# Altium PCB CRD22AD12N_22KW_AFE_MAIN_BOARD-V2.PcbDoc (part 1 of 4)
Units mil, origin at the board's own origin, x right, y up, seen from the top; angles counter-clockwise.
Board outline 14411 x 7330.3 mil, 4 copper layers (TOP, GND02, POWER03, BOTTOM), stack 78.531 mil thick; 589 components, 281 nets, 1401 pads, 282 vias.
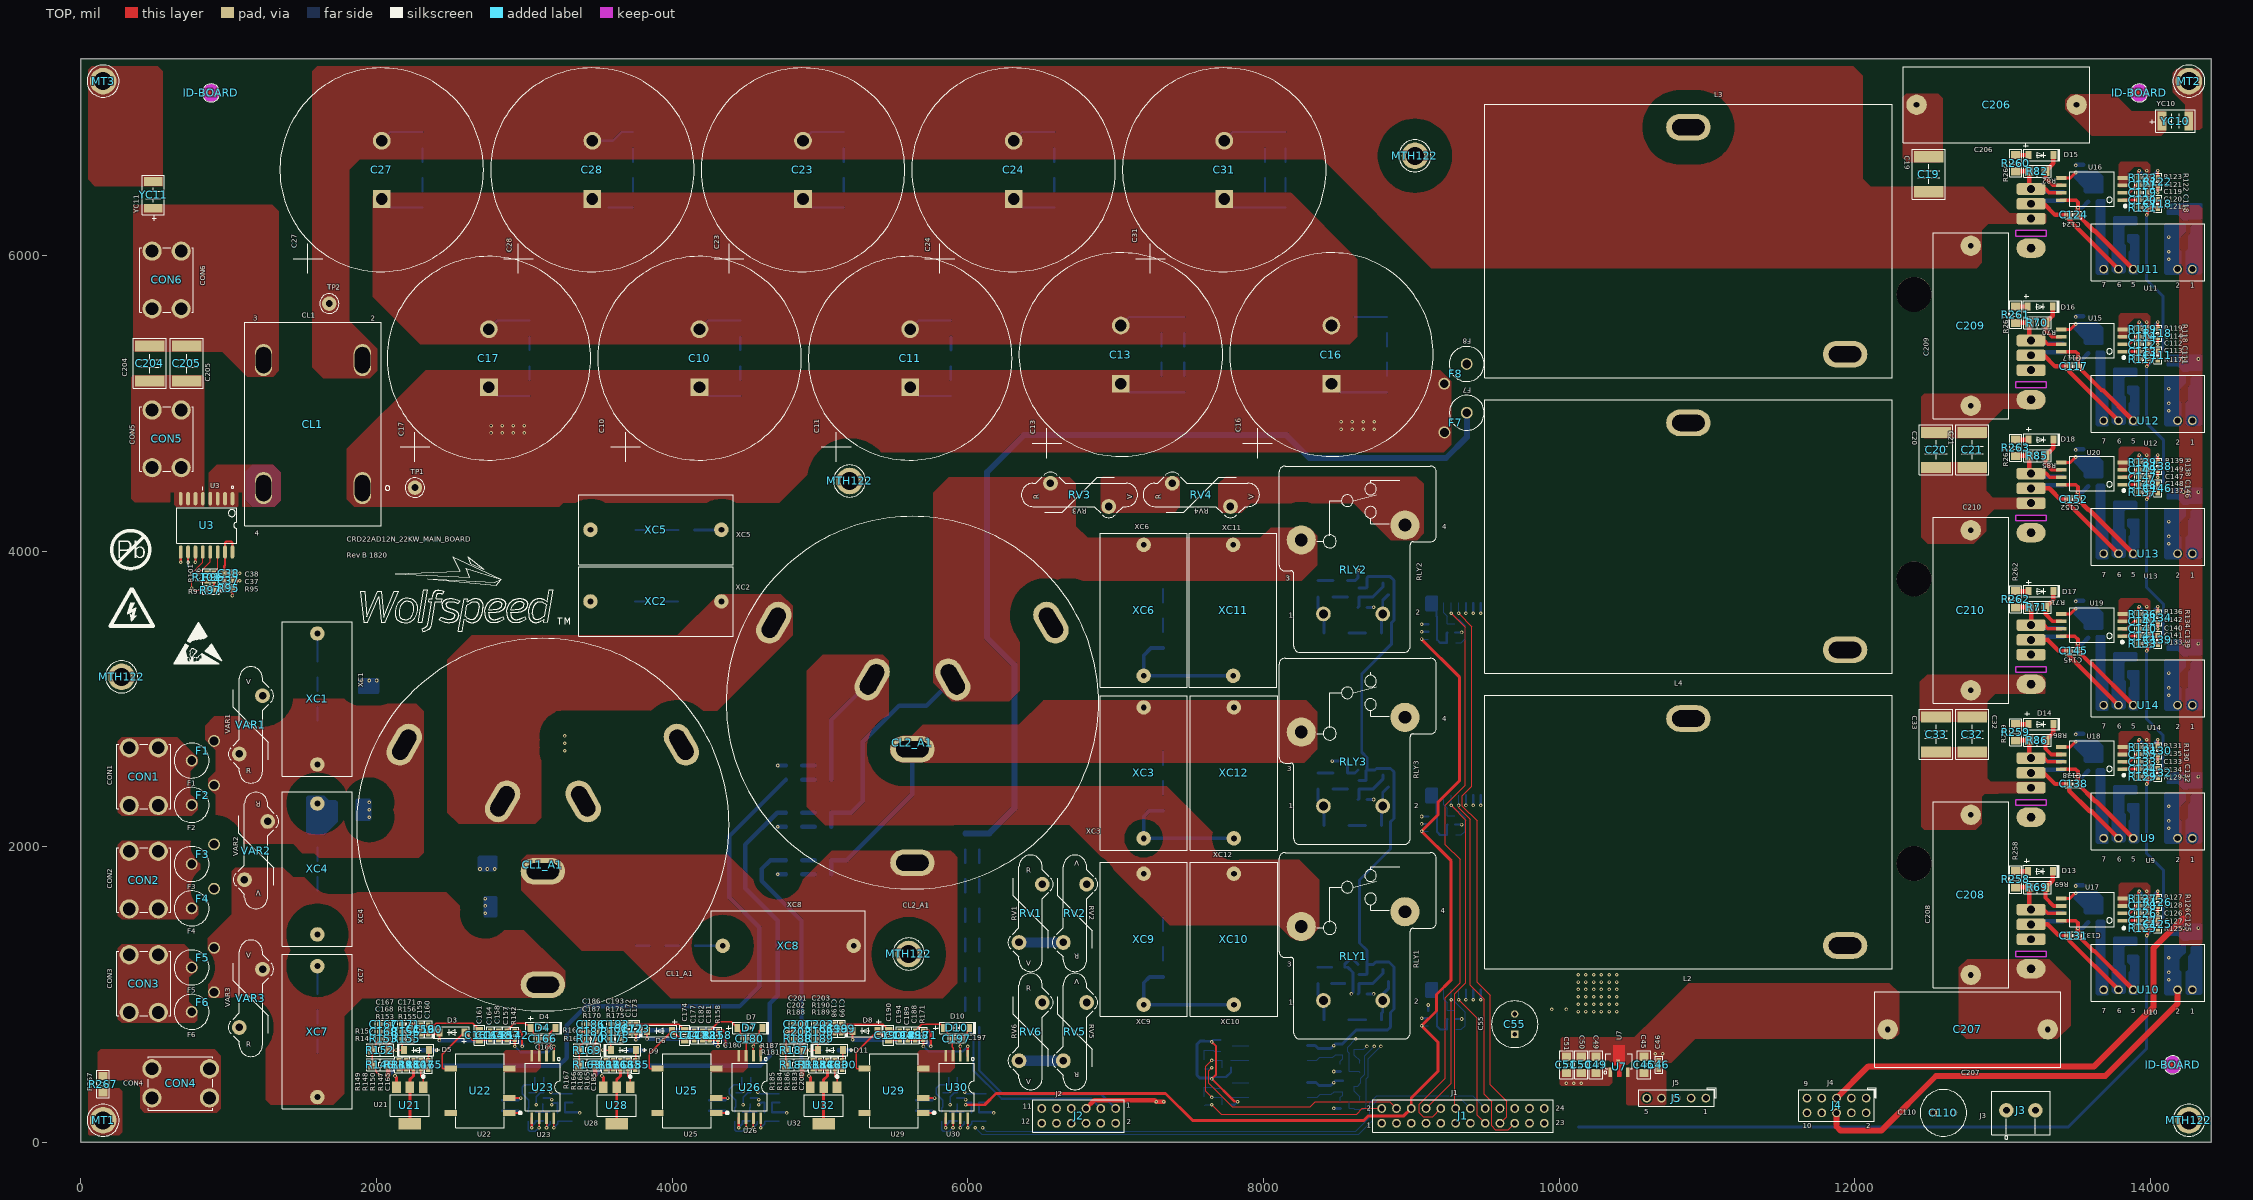
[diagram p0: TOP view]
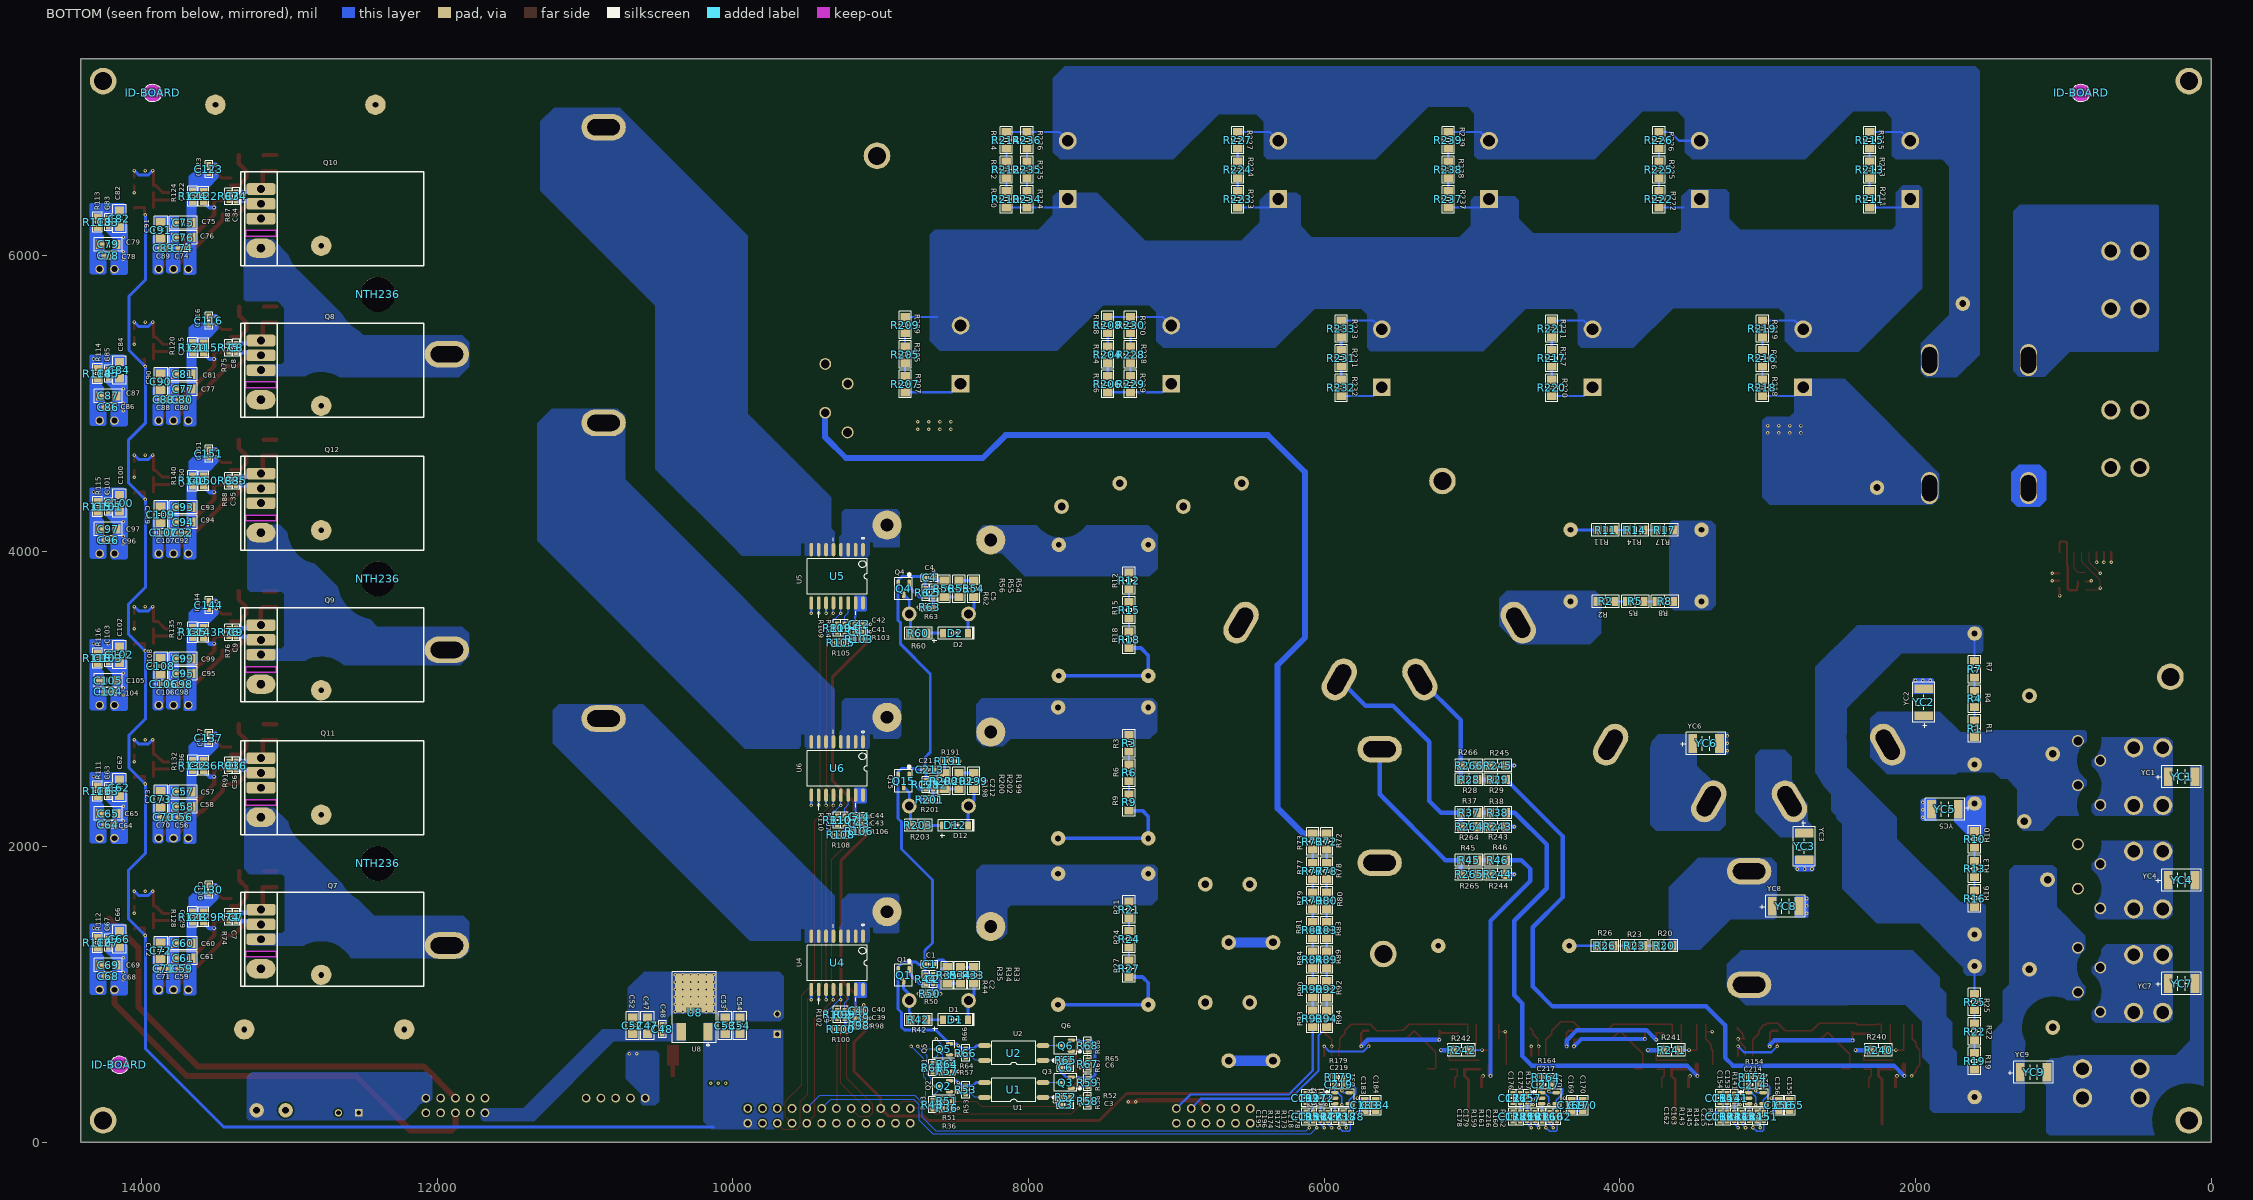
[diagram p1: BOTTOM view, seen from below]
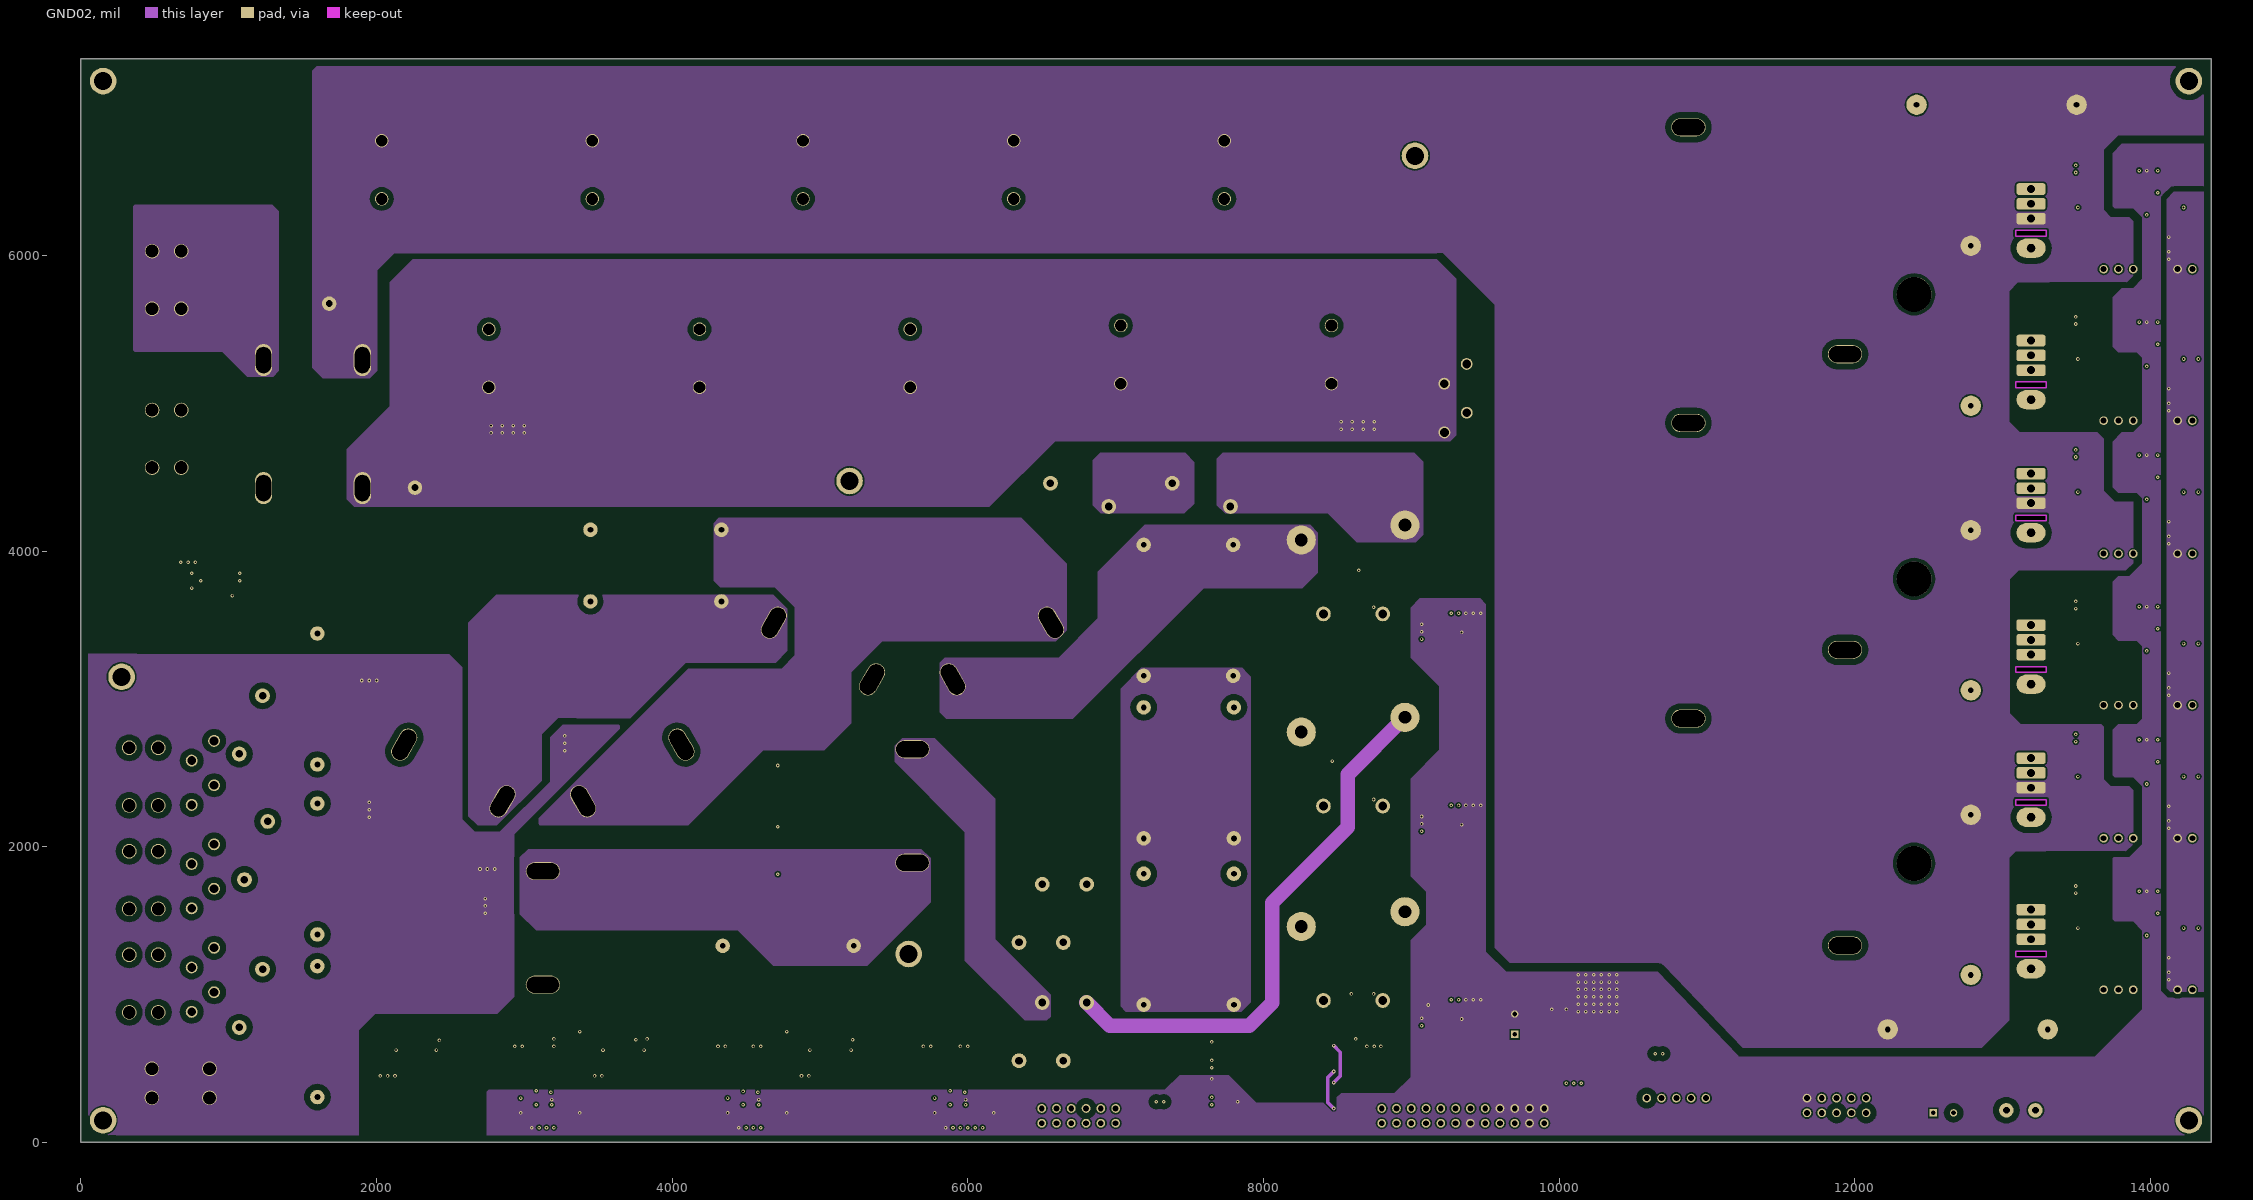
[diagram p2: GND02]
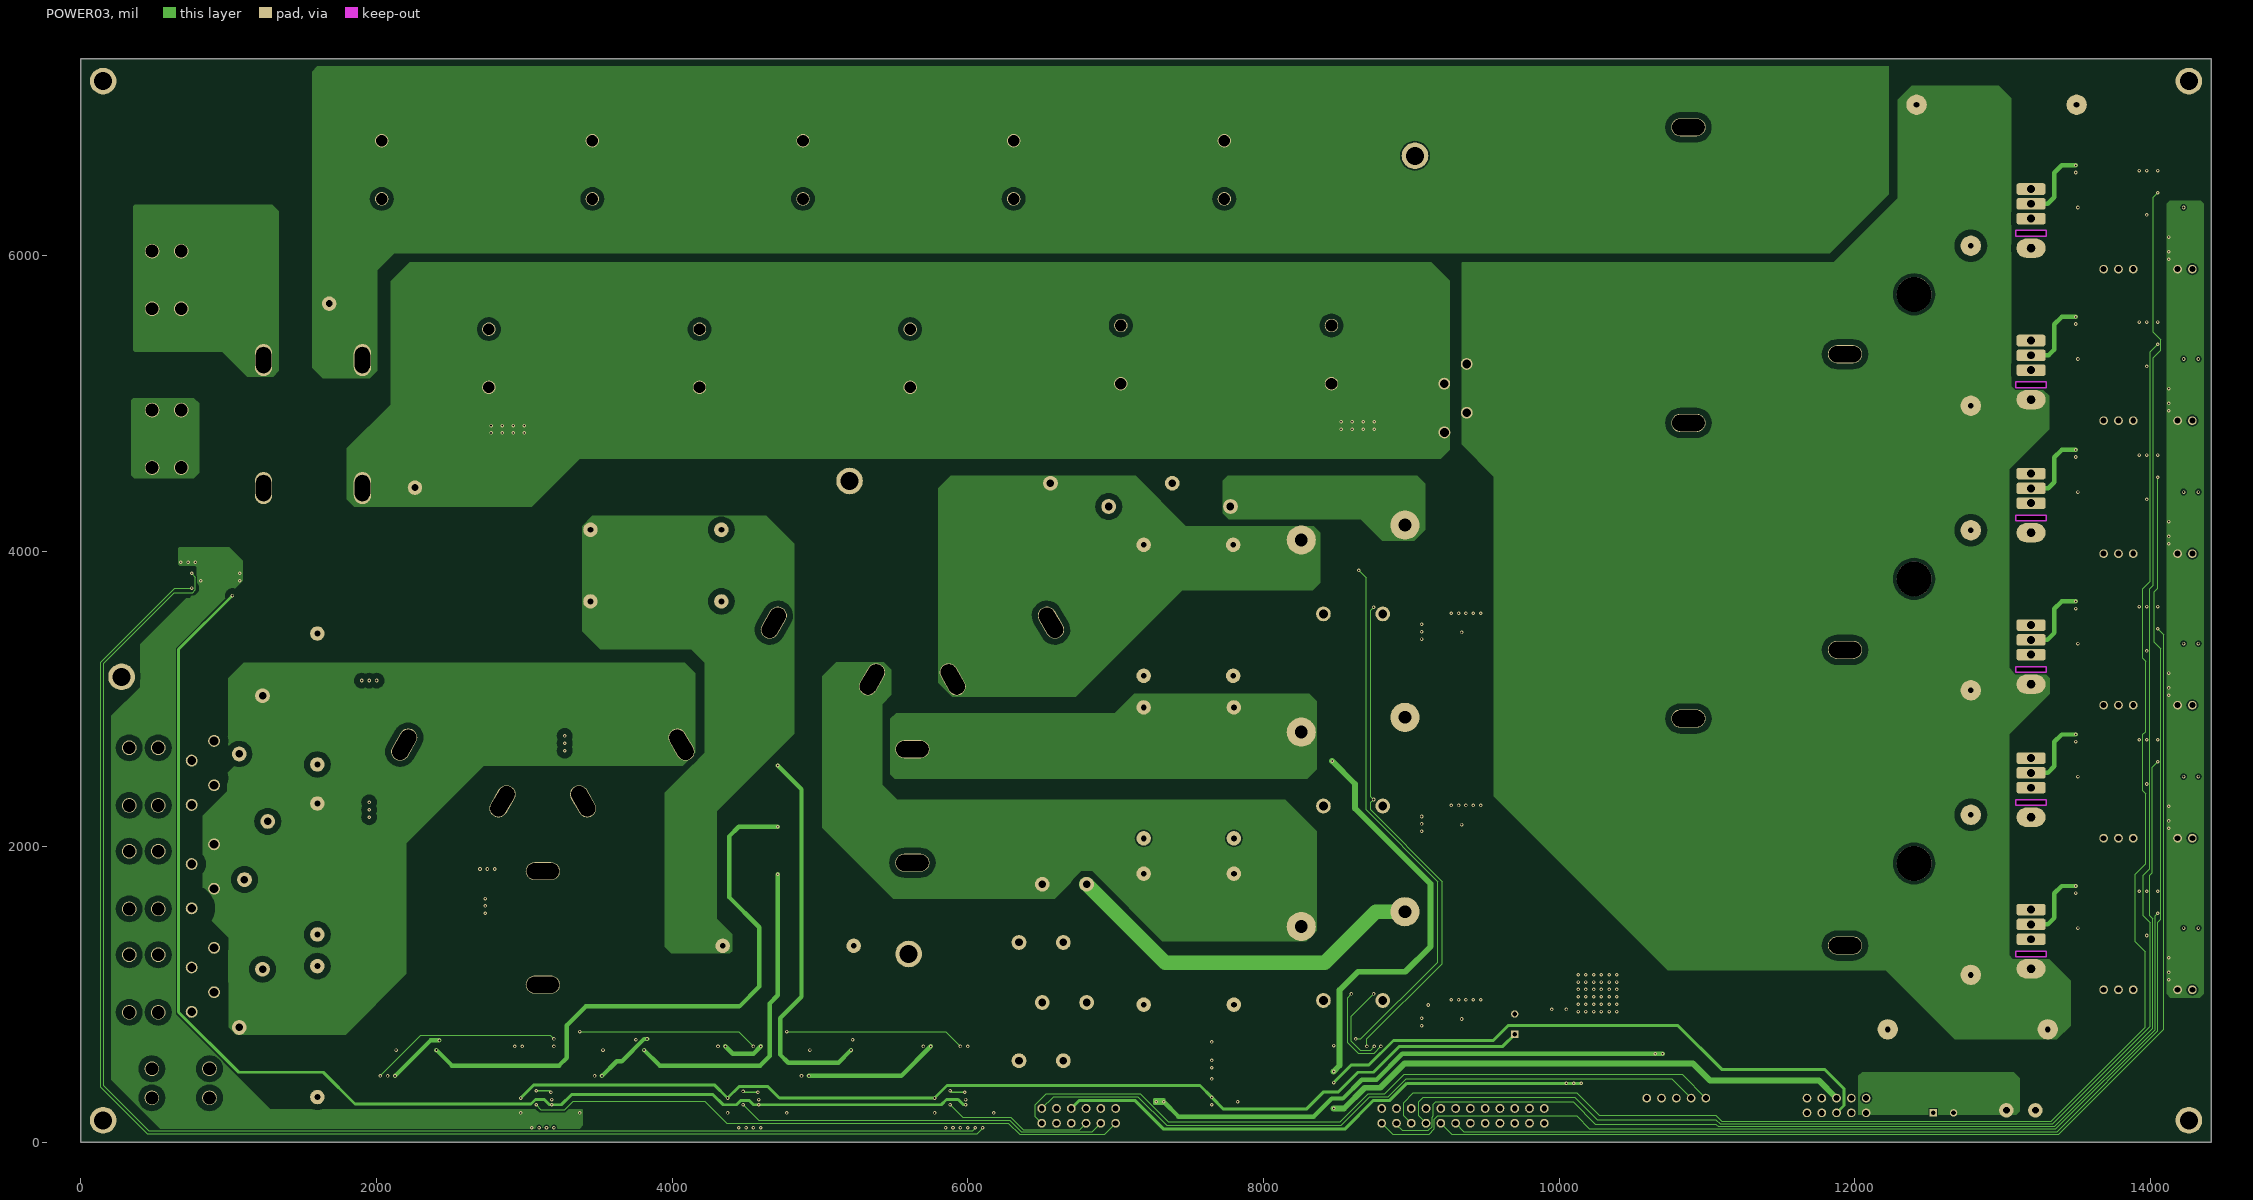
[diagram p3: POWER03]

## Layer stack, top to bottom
Top Solder: solder mask 0.4, Solder Resist, Dk 3.5
TOP: signal copper 2.7559
Dielectric 1: core 4.4153, FR-4, Dk 4.5
GND02: signal copper 2.4
Dielectric2: core 59.389, FR-4, Dk 4.5
POWER03: signal copper 2.4
Dielectric3: core 4.4153, FR-4, Dk 4.5
BOTTOM: signal copper 2.7559
Bottom Solder: solder mask 0.4, Solder Resist, Dk 3.5

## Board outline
0,7330.3 14411,7330.3 14411,0 0,0
cut-out: 13088.63,1255.32 13088.63,1294.68 13297.29,1294.68 13297.29,1255.32
cut-out: 13088.63,2280.31 13088.63,2319.68 13297.29,2319.68 13297.29,2280.31
cut-out: 13088.63,3180.32 13297.29,3180.32 13297.29,3219.68 13088.63,3219.68
cut-out: 13088.63,4205.31 13297.29,4205.31 13297.29,4244.68 13088.63,4244.68
cut-out: 13088.63,5105.31 13297.29,5105.31 13297.29,5144.68 13088.63,5144.68
cut-out: 13088.63,6130.31 13297.29,6130.31 13297.29,6169.68 13088.63,6169.68
cut-out: 13088.63,5144.68 13297.29,5144.68 13297.29,5105.31 13088.63,5105.31 13297.29,5105.31 13297.29,5144.68 13088.63,5144.68 13088.63,5105.31
cut-out: 13088.63,4244.68 13297.29,4244.68 13297.29,4205.31 13088.63,4205.31 13297.29,4205.31 13297.29,4244.68 13088.63,4244.68 13088.63,4205.31
cut-out: 13088.63,3219.68 13297.29,3219.68 13297.29,3180.32 13088.63,3180.32 13297.29,3180.32 13297.29,3219.68 13088.63,3219.68 13088.63,3180.32
cut-out: 13088.63,2319.68 13297.29,2319.68 13297.29,2280.31 13088.63,2280.31 13297.29,2280.31 13297.29,2319.68 13088.63,2319.68 13088.63,2280.31
cut-out: 13088.63,6169.68 13297.29,6169.68 13297.29,6130.31 13088.63,6130.31 13297.29,6130.31 13297.29,6169.68 13088.63,6169.68 13088.63,6130.31
cut-out: 13297.29,1255.31 13297.29,1294.68 13088.63,1294.68 13088.63,1255.31 13088.63,1294.68 13297.29,1294.68 13297.29,1255.31 13088.63,1255.31

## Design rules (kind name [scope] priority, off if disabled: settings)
Clearance "Clearance (Class DI-GAO)_INT" [(InNetClass('DI') AND OnLayer('Multi-Layer') OR OnLayer('GND02') OR OnLayer('POWER03')) vs (InNetClass('GAO') AND OnLayer('Multi-Layer') OR OnLayer('GND02') OR OnLayer('POWER03'))] p1: gap=40 ignorepadtopadclearanceinfootprint=FALSE except(5: Track-THPad Track-Via; 10: Arc-Arc Arc-Track Arc-SMDPad Arc-THPad Track-Track Track-SMDPad Track-Fill Track-Poly Track-Region Track-Text Track-Hole SMDPad-SMDPad SMDPad-THPad SMDPad-Via SMDPad-Fill SMDPad-Poly SMDPad-Region SMDPad-Text SMDPad-Hole; 12: Arc-Text THPad-Poly) // Internal Layers
Clearance Clearance_2 [All] p2: gap=10 ignorepadtopadclearanceinfootprint=FALSE except(0: SMDPad-Via Text-Hole; 5: Arc-Via Track-Via; 6: Track-Track Track-SMDPad Track-THPad; 8: Arc-Hole Track-Hole SMDPad-Hole THPad-Hole Via-Hole Fill-Hole Poly-Hole Region-Hole Hole-Hole; 9.1: SMDPad-SMDPad SMDPad-THPad THPad-THPad; 15: Fill-Poly Fill-Region Poly-Region)
Clearance "Clearance (Class DI-GAO)" [InNetClass('DI') vs InNetClass('GAO')] p3 off: gap=160 ignorepadtopadclearanceinfootprint=FALSE // (Class DI-GAO)
Clearance "Clearance for netlist (Same net)" [InNet('AC_LA') Or InNet('AC_LA1') Or InNet('AC_LAP') Or InNet('AC_LB') Or InNet('AC_LB1') Or InNet('AC_LBP') Or InNet('AC_LC') Or InNet('AC_LC1') Or InNet('AC_LCP') Or InNet('AGND') Or InNet('GGND') Or InNet('GND_EARTH') Or InNet('IGND') Or InNet('LA') Or InNet('LB') Or InNet('LC') Or InNet('N17896613') Or InNet('N17896948') Or InNet('N17898200') Or InNet('N17898311') Or InNet('N17908016') Or InNet('N17908018') Or InNet('N17908020') Or InNet('N17908062') Or InNet('N17911032') Or InNet('N17911109') Or InNet('N17911239') Or InNet('N17911323') Or InNet('N179113761') Or InNet('N17916066') Or InNet('N17916108') Or InNet('N17916243') Or InNet('N17920487') Or InNet('N18077724') Or InNet('N18077784') Or InNet('PGND') Or InNet('VPFC') vs InPolygon Or IsArc Or IsFill Or IsPad Or IsRegion Or IsThruPin Or IsThruVia Or IsTrack] p4 off: gap=10 ignorepadtopadclearanceinfootprint=FALSE except(0: Text-Hole; 5: Arc-Via Track-Via; 8: Arc-Hole Track-Hole SMDPad-Hole THPad-Hole Via-Hole Fill-Hole Poly-Hole Region-Hole Hole-Hole; 9.1: SMDPad-SMDPad SMDPad-THPad THPad-THPad; 15: Fill-Poly Fill-Region Poly-Region)
Clearance "Clearance for netlist" [InNet('AC_LA') Or InNet('AC_LA1') Or InNet('AC_LAP') Or InNet('AC_LB') Or InNet('AC_LB1') Or InNet('AC_LBP') Or InNet('AC_LC') Or InNet('AC_LC1') Or InNet('AC_LCP') Or InNet('AGND') Or InNet('GGND') Or InNet('GND_EARTH') Or InNet('IGND') Or InNet('LA') Or InNet('LB') Or InNet('LC') Or InNet('N17896613') Or InNet('N17896948') Or InNet('N17898200') Or InNet('N17898311') Or InNet('N17908016') Or InNet('N17908018') Or InNet('N17908020') Or InNet('N17908062') Or InNet('N17911032') Or InNet('N17911109') Or InNet('N17911239') Or InNet('N17911323') Or InNet('N179113761') Or InNet('N17916066') Or InNet('N17916108') Or InNet('N17916243') Or InNet('N17920487') Or InNet('N18077724') Or InNet('N18077784') Or InNet('PGND') Or InNet('VPFC') vs InPolygon Or IsArc Or IsFill Or IsPad Or IsRegion Or IsThruPin Or IsThruVia Or IsTrack] p5 off: gap=10 ignorepadtopadclearanceinfootprint=FALSE except(0: Text-Hole; 5: Arc-Via Track-Via; 8: Arc-Hole Track-Hole SMDPad-Hole THPad-Hole Via-Hole Fill-Hole Poly-Hole Region-Hole Hole-Hole; 9.1: SMDPad-SMDPad SMDPad-THPad THPad-THPad; 15: Fill-Poly Fill-Region Poly-Region)
Clearance "Clearance (Same Net)" [All] p6 off: gap=10 ignorepadtopadclearanceinfootprint=FALSE except(0: Arc-Fill Arc-Poly Arc-Region Track-Fill Track-Poly Track-Region SMDPad-Via SMDPad-Fill SMDPad-Poly SMDPad-Region Via-Fill Via-Poly Via-Region Fill-Poly Poly-Poly Text-Hole; 5: Arc-Via Track-Via; 8: Arc-Hole Track-Hole SMDPad-Hole THPad-Hole Via-Hole Fill-Hole Poly-Hole Region-Hole Hole-Hole; 9.1: SMDPad-SMDPad SMDPad-THPad THPad-THPad; 15: Fill-Fill Fill-Region Poly-Region Region-Region)
ComponentClearance [All] p1: gap=5 collisioncheckmode=3 verticalgap=10 showdistances=FALSE
Creepage [InNetClass('DI') vs InNetClass('GAO')] p1 off: checkdistance=160 ignoreinternallayers=FALSE // DI-GAO 160mil spacing
Height [All] p1: minheight=0 maxheight=3000 prefheight=500
HoleSize [All] p1: absolutevalues=TRUE maxlimit=250 minlimit=1 maxpercent=80.000 minpercent=20.000
PlaneConnect [All] p1: planeconnectstyle=Direct reliefexpansion=20 reliefentries=4 reliefconductorwidth=10 reliefairgap=10
PolygonConnect [All] p1: connectstyle=Direct reliefconductorwidth=10 reliefentries=4 polygonreliefangle="90 Angle" airgapwidth=10
RoutingVias [All] p1: holewidth=28 width=50 viastyle="Through Hole" minholewidth=28 minwidth=50 maxholewidth=28 maxwidth=50
SolderMaskExpansion [All] p1: expansion=4 istentingtop=FALSE
ViasUnderSMD [InComponent('U8')] p1: allowed=TRUE
Width [All] p1: maxlimit=300 minlimit=6 preferedwidth=10
26 further rules are at their usual default settings.

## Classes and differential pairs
net class R_DI: N17911032 N17911109 N17911239 N17911323 N18077724 N18077784 N179113761
net class DI: AGND GGND GND_EARTH IGND PGND
net class GAO: AC_LA AC_LA1 AC_LAP AC_LB AC_LB1 AC_LBP AC_LC AC_LC1 AC_LCP LA LB LC N17896613 N17896948 N17898200 N17898311 N17908016 N17908018 N17908020 N17908062 N17916066 N17916108 N17916243 N17920487 VPFC

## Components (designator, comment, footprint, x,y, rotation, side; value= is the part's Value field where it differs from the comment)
C1 "CAP NP_C0603_0.1UF" C0603 8670,1205 r0 bottom
C2 "CAP NP_C0603_1N" C0603 8645,1105 r270 bottom
C3 "CAP NP_C0603_0U1" C0603 7750,255 r0 bottom
C4 "CAP NP_C0603_0.1UF" C0603 8670,3820 r0 bottom
C5 "CAP NP_C0603_1N" C0603 8645,3720 r270 bottom
C6 "CAP NP_C0603_0U1" C0603 7750,505 r0 bottom
C7 "CAP NP_C0603_1N" C0603 13360.68,1525 r270 bottom
C8 "CAP NP_C0603_1N" C0603 13360.68,5375 r270 bottom
C9 "CAP NP_C0603_1N" C0603 13360.68,3450 r270 bottom
C10 "CAP POL_ECAP_D35P7_25_500V 680U" ECAP_D35P7_25 4185,5305 r90 top
C11 "CAP POL_ECAP_D35P7_25_500V 680U" ECAP_D35P7_25 5610,5305 r90 top
C13 "CAP POL_ECAP_D35P7_25_500V 680U" ECAP_D35P7_25 7035,5330 r90 top
C16 "CAP POL_ECAP_D35P7_25_500V 680U" ECAP_D35P7_25 8460,5330 r90 top
C17 "CAP POL_ECAP_D35P7_25_500V 680U" ECAP_D35P7_25 2760,5305 r90 top
C19 "CAP NP_C2220_0U1" C2220 12500,6550 r270 top
C20 "CAP NP_C2220_0U1" C2220 12550,4685 r270 top
C21 "CAP NP_C2220_0U1" C2220 12795,4685 r270 top
C23 "CAP POL_ECAP_D35P7_25_500V 680U" ECAP_D35P7_25 4885,6580 r90 top
C24 "CAP POL_ECAP_D35P7_25_500V 680U" ECAP_D35P7_25 6310,6580 r90 top
C27 "CAP POL_ECAP_D35P7_25_500V 680U" ECAP_D35P7_25 2035,6580 r90 top
C28 "CAP POL_ECAP_D35P7_25_500V 680U" ECAP_D35P7_25 3460,6580 r90 top
C31 "CAP POL_ECAP_D35P7_25_500V 680U" ECAP_D35P7_25 7735,6580 r90 top
C32 "CAP NP_C2220_0U1" C2220 12795,2760 r270 top
C33 "CAP NP_C2220_0U1" C2220 12550,2760 r270 top
C34 "CAP NP_C0603_1N" C0603 13360.68,6400 r270 bottom
C35 "CAP NP_C0603_1N" C0603 13360.68,4475 r270 bottom
C36 "CAP NP_C0603_1N" C0603 13360.68,2550 r270 bottom
C37 "CAP NP_C0603_0.1U" C0603 1000,3800 r0 top
C38 "CAP NP_C0603_1U" C0603 1000,3850 r0 top
C39 "CAP NP_C0603_0.1U" C0603 9145,840 r180 bottom
C40 "CAP NP_C0603_1U" C0603 9145,890 r180 bottom
C41 "CAP NP_C0603_0.1U" C0603 9145,3455 r180 bottom
C42 "CAP NP_C0603_1U" C0603 9145,3505 r180 bottom
C43 "CAP NP_C0603_0.1U" C0603 9145,2155 r180 bottom
C44 "CAP NP_C0603_1U" C0603 9145,2205 r180 bottom
C45 "CAP NP_C1206_10U" C1206 10575,525 r90 top
C46 "CAP NP_C0603_1U" C0603 10675,525 r270 top
C47 "CAP NP_C1206_10U" C1206 10577.76,790.75 r90 bottom
C48 "CAP NP_C0603_1U" C0603 10477.76,765.75 r270 bottom
C49 "CAP NP_C1206_1U" C1206 10250,525 r90 top
C50 "CAP NP_C1206_22U" C1206 10150,525 r90 top
C51 "CAP NP_C1206_22U" C1206 10050,525 r90 top
C52 "CAP NP_C1206_10U" C1206 10677.76,790.75 r90 bottom
C53 "CAP NP_C1206_10U" C1206 10052.76,790.75 r90 bottom
C54 "CAP NP_C1206_10U" C1206 9952.76,790.75 r90 bottom
C55 "CAP POL_ECAP_D8P3_5_25V 220UF" ECAP_D8P3_5 9700,800 r90 top
C56 "CAP NP_C0603_1UF" C0603 13725,2200 r0 bottom
C57 "CAP NP_C1206_4U7" C1206 13720,2372 r180 bottom
C58 "CAP NP_C1206_10UF" C1206 13720,2272 r180 bottom
C59 "CAP NP_C0603_1UF" C0603 13725,1175 r0 bottom
C60 "CAP NP_C1206_4U7" C1206 13720,1347 r180 bottom
C61 "CAP NP_C1206_10UF" C1206 13720,1247 r180 bottom
C62 "CAP NP_C1206_10UF" C1206 14150,2400 r90 bottom
C63 "CAP NP_C0603_1UF" C0603 14225,2375 r270 bottom
C64 "CAP NP_C0603_0U1" C0603 14225,2150 r180 bottom
C65 "CAP NP_C1206_2U2" C1206 14225,2225 r0 bottom
C66 "CAP NP_C1206_10UF" C1206 14150,1375 r90 bottom
C67 "CAP NP_C0603_1UF" C0603 14225,1350 r270 bottom
C68 "CAP NP_C0603_0U1" C0603 14225,1125 r180 bottom
C69 "CAP NP_C1206_2U2" C1206 14225,1200 r0 bottom
C70 "CAP NP_C0603_1UF" C0603 13850,2200 r0 bottom
C71 "CAP NP_C0603_1UF" C0603 13850,1175 r0 bottom
C72 "CAP NP_C1206_10UF" C1206 13870,1297 r90 bottom
C73 "CAP NP_C1206_10UF" C1206 13870,2322 r90 bottom
C74 "CAP NP_C0603_1UF" C0603 13725,6050 r0 bottom
C75 "CAP NP_C1206_4U7" C1206 13720,6222 r180 bottom
C76 "CAP NP_C1206_10UF" C1206 13720,6122 r180 bottom
C77 "CAP NP_C1206_10UF" C1206 13720,5097 r180 bottom
C78 "CAP NP_C0603_0U1" C0603 14225,6000 r180 bottom
C79 "CAP NP_C1206_2U2" C1206 14225,6075 r0 bottom
C80 "CAP NP_C0603_1UF" C0603 13725,5025 r0 bottom
C81 "CAP NP_C1206_4U7" C1206 13720,5197 r180 bottom
C82 "CAP NP_C1206_10UF" C1206 14150,6250 r90 bottom
C83 "CAP NP_C0603_1UF" C0603 14225,6225 r270 bottom
C84 "CAP NP_C1206_10UF" C1206 14150,5225 r90 bottom
C85 "CAP NP_C0603_1UF" C0603 14225,5200 r270 bottom
C86 "CAP NP_C0603_0U1" C0603 14225,4975 r180 bottom
C87 "CAP NP_C1206_2U2" C1206 14225,5050 r0 bottom
C88 "CAP NP_C0603_1UF" C0603 13850,5025 r0 bottom
C89 "CAP NP_C0603_1UF" C0603 13850,6050 r0 bottom
C90 "CAP NP_C1206_10UF" C1206 13870,5147 r90 bottom
C91 "CAP NP_C1206_10UF" C1206 13870,6172 r90 bottom
C92 "CAP NP_C0603_1UF" C0603 13725,4125 r0 bottom
C93 "CAP NP_C1206_4U7" C1206 13720,4297 r180 bottom
C94 "CAP NP_C1206_10UF" C1206 13720,4197 r180 bottom
C95 "CAP NP_C1206_10UF" C1206 13720,3172 r180 bottom
C96 "CAP NP_C0603_0U1" C0603 14225,4075 r180 bottom
C97 "CAP NP_C1206_2U2" C1206 14225,4150 r0 bottom
C98 "CAP NP_C0603_1UF" C0603 13725,3100 r0 bottom
C99 "CAP NP_C1206_4U7" C1206 13720,3272 r180 bottom
C100 "CAP NP_C1206_10UF" C1206 14150,4325 r90 bottom
C101 "CAP NP_C0603_1UF" C0603 14225,4300 r270 bottom
C102 "CAP NP_C1206_10UF" C1206 14150,3300 r90 bottom
C103 "CAP NP_C0603_1UF" C0603 14225,3275 r270 bottom
C104 "CAP NP_C0603_0U1" C0603 14225,3050 r180 bottom
C105 "CAP NP_C1206_2U2" C1206 14225,3125 r0 bottom
C106 "CAP NP_C0603_1UF" C0603 13850,3100 r0 bottom
C107 "CAP NP_C0603_1UF" C0603 13850,4125 r0 bottom
C108 "CAP NP_C1206_10UF" C1206 13870,3222 r90 bottom
C109 "CAP NP_C1206_10UF" C1206 13870,4247 r90 bottom
C110 "CAP POL_ECAP_D8P3_5_25V 220UF" ECAP_D8P3_5 12600,200 r0 top
C111 "CAP NP_C0603_2.2U" C0603 14050,5325 r90 top
C112 "CAP NP_C0603_1U" C0603 13950,5400 r0 top
C113 "CAP NP_C0603_0.1U" C0603 13950,5350 r0 top
C114 "CAP NP_C0603_0.33N" C0603 13950,5450 r0 top
C115 "CAP NP_C0805_2.2U" C0805 13580.34,5375 r270 bottom
C116 "CAP NP_C0603_1U" C0603 13545.34,5560 r90 bottom
C117 "CAP NP_C0603_1U" C0603 13480.34,5250 r0 top
C118 "CAP NP_C0603_2.2U" C0603 14050,6350 r90 top
C119 "CAP NP_C0603_1U" C0603 13950,6425 r0 top
C120 "CAP NP_C0603_0.1U" C0603 13950,6375 r0 top
C121 "CAP NP_C0603_0.33N" C0603 13950,6475 r0 top
C122 "CAP NP_C0805_2.2U" C0805 13580.34,6400 r270 bottom
C123 "CAP NP_C0603_1U" C0603 13545.34,6585 r90 bottom
C124 "CAP NP_C0603_1U" C0603 13480.34,6275 r0 top
C125 "CAP NP_C0603_2.2U" C0603 14050,1475 r90 top
C126 "CAP NP_C0603_1U" C0603 13950,1550 r0 top
C127 "CAP NP_C0603_0.1U" C0603 13950,1500 r0 top
C128 "CAP NP_C0603_0.33N" C0603 13950,1600 r0 top
C129 "CAP NP_C0805_2.2U" C0805 13580.34,1525 r270 bottom
C130 "CAP NP_C0603_1U" C0603 13545.34,1710 r90 bottom
C131 "CAP NP_C0603_1U" C0603 13480.34,1400 r0 top
C132 "CAP NP_C0603_2.2U" C0603 14050,2500 r90 top
C133 "CAP NP_C0603_1U" C0603 13950,2575 r0 top
C134 "CAP NP_C0603_0.1U" C0603 13950,2525 r0 top
C135 "CAP NP_C0603_0.33N" C0603 13950,2625 r0 top
C136 "CAP NP_C0805_2.2U" C0805 13580.34,2550 r270 bottom
C137 "CAP NP_C0603_1U" C0603 13545.34,2735 r90 bottom
C138 "CAP NP_C0603_1U" C0603 13480.34,2425 r0 top
C139 "CAP NP_C0603_2.2U" C0603 14050,3400 r90 top
C140 "CAP NP_C0603_1U" C0603 13950,3475 r0 top
C141 "CAP NP_C0603_0.1U" C0603 13950,3425 r0 top
C142 "CAP NP_C0603_0.33N" C0603 13950,3525 r0 top
C143 "CAP NP_C0805_2.2U" C0805 13580.34,3450 r270 bottom
C144 "CAP NP_C0603_1U" C0603 13545.34,3635 r90 bottom
C145 "CAP NP_C0603_1U" C0603 13480.34,3325 r0 top
C146 "CAP NP_C0603_2.2U" C0603 14050,4425 r90 top
C147 "CAP NP_C0603_1U" C0603 13950,4500 r0 top
C148 "CAP NP_C0603_0.1U" C0603 13950,4450 r0 top
C149 "CAP NP_C0603_0.33N" C0603 13950,4550 r0 top
C150 "CAP NP_C0805_2.2U" C0805 13580.34,4475 r270 bottom
C151 "CAP NP_C0603_1U" C0603 13545.34,4660 r90 bottom
C152 "CAP NP_C0603_1U" C0603 13480.34,4350 r0 top
C153 "CAP NP_C0603_0.1U" C0603 3275,300 r270 bottom
C154 "CAP NP_C0603_0.01U" C0603 3325,300 r270 bottom
C155 "CAP NP_C0805_4.7U" C0805 2850,250 r90 bottom
C156 "CAP NP_C0805_4.7U" C0805 2925,250 r90 bottom
C157 "CAP NP_C0603_0.1U" C0603 2880,725 r270 top
C158 "CAP NP_C0603_1U" C0603 2825,725 r270 top
C159 "CAP NP_C0603_0.1U" C0603 2300,765 r270 top
C160 "CAP NP_C0603_1U" C0603 2350,765 r270 top
C161 "CAP NP_C0805_4.7U" C0805 2695,725 r270 top
C162 "CAP NP_C0603_0.1U" C0603 3325,175 r90 bottom
C163 "CAP NP_C0603_0.01U" C0603 3275,175 r90 bottom
C164 "CAP NP_C0603_0.1U" C0603 2770,725 r270 top
C165 "CAP NP_C0603_0.1U" C0603 2350,525 r90 top
C166 "CAP NP_C0603_0.1U" C0603 3125,700 r180 top
C167 "CAP NP_C0603_0.1U" C0603 2050,800 r0 top
C168 "CAP NP_C0603_DNP" C0603 2050,750 r0 top
C169 "CAP NP_C0805_4.7U" C0805 4325,250 r90 bottom
C170 "CAP NP_C0805_4.7U" C0805 4250,250 r90 bottom
C171 "CAP NP_C0603_0.1U" C0603 2200,800 r0 top
C172 "CAP NP_C0603_0.1U" C0603 3705,770 r270 top
C173 "CAP NP_C0603_1U" C0603 3755,770 r270 top
C174 "CAP NP_C0805_4.7U" C0805 4085,725 r270 top
C175 "CAP NP_C0603_0.1U" C0603 4675,300 r270 bottom
C176 "CAP NP_C0603_0.01U" C0603 4725,300 r270 bottom
C177 "CAP NP_C0603_0.1U" C0603 4150,725 r270 top
C178 "CAP NP_C0603_0.1U" C0603 4725,175 r90 bottom
C179 "CAP NP_C0603_0.01U" C0603 4675,175 r90 bottom
C180 "CAP NP_C0603_0.1U" C0603 4525,700 r180 top
C181 "CAP NP_C0603_0.1U" C0603 4255,725 r270 top
C182 "CAP NP_C0603_1U" C0603 4205,725 r270 top
C183 "CAP NP_C0805_4.7U" C0805 5725,250 r90 bottom
C184 "CAP NP_C0805_4.7U" C0805 5650,250 r90 bottom
C185 "CAP NP_C0603_0.1U" C0603 3750,525 r90 top
C186 "CAP NP_C0603_0.1U" C0603 3450,800 r0 top
C187 "CAP NP_C0603_DNP" C0603 3450,750 r0 top
C188 "CAP NP_C0603_0.1U" C0603 5645,725 r270 top
C189 "CAP NP_C0603_1U" C0603 5595,725 r270 top
C190 "CAP NP_C0805_4.7U" C0805 5465,725 r270 top
C191 "CAP NP_C0603_0.1U" C0603 6075,300 r270 bottom
C192 "CAP NP_C0603_0.01U" C0603 6125,300 r270 bottom
C193 "CAP NP_C0603_0.1U" C0603 3615,800 r0 top
C194 "CAP NP_C0603_0.1U" C0603 5540,725 r270 top
C195 "CAP NP_C0603_0.1U" C0603 6125,175 r90 bottom
C196 "CAP NP_C0603_0.01U" C0603 6075,175 r90 bottom
C197 "CAP NP_C0603_0.1U" C0603 5925,700 r180 top
C198 "CAP NP_C0603_0.1U" C0603 5095,770 r270 top
C199 "CAP NP_C0603_1U" C0603 5145,770 r270 top
C200 "CAP NP_C0603_0.1U" C0603 5150,525 r90 top
C201 "CAP NP_C0603_0.1U" C0603 4850,800 r0 top
C202 "CAP NP_C0603_DNP" C0603 4850,750 r0 top
C203 "CAP NP_C0603_0.1U" C0603 5000,800 r0 top
C204 "CAP NP_C2220_0U1" C2220 465,5270 r90 top
C205 "CAP NP_C2220_0U1" C2220 715,5270 r90 top
C206 "CAP NP_CAPFILM_31_5X12_5MM_2.2U" CAPFILM_31_5X12_5MM 12960,7020 r0 top
C207 "CAP NP_CAPFILM_31_5X12_5MM_2.2U" CAPFILM_31_5X12_5MM 12765,765 r180 top
C208 "CAP NP_CAPFILM_31_5X12_5MM_2.2U" CAPFILM_31_5X12_5MM 12785.68,1675 r90 top
C209 "CAP NP_CAPFILM_31_5X12_5MM_2.2U" CAPFILM_31_5X12_5MM 12785.68,5525 r90 top
C210 "CAP NP_CAPFILM_31_5X12_5MM_2.2U" CAPFILM_31_5X12_5MM 12785.68,3600 r90 top
C212 "CAP NP_C0603_1N" C0603 8645,2420 r270 bottom
C213 "CAP NP_C0603_0.1UF" C0603 8670,2520 r0 bottom
C214 "CAP NP_C0603_NA" C0603 3100,390 r0 bottom
C215 "CAP NP_C0603_NA" C0603 3075,175 r270 bottom
C216 "CAP NP_C0603_NA" C0603 4525,175 r270 bottom
C217 "CAP NP_C0603_NA" C0603 4500,390 r0 bottom
C218 "CAP NP_C0603_NA" C0603 5875,175 r270 bottom
C219 "CAP NP_C0603_NA" C0603 5900,390 r0 bottom
CL1 "TRNSFMR 67125450_0_CM_4P_6TS" CM_4P 1570,4860 r90 top
CL1_A1 "126LNS_5_LCM1_8U" LCM1 3125,2150 r0 top
CL2_A1 "126LNS_5_LCM1_8U" LCM1 5625,2975 r0 top
CON1 "CONNECTER_THREAD4_9P9X5_1110X92" THREAD4_9P9X5_1110X920 425,2475 r270 top
CON2 "CONNECTER_THREAD4_9P9X5_1110X92" THREAD4_9P9X5_1110X920 425,1775 r270 top
CON3 "CONNECTER_THREAD4_9P9X5_1110X92" THREAD4_9P9X5_1110X920 425,1075 r270 top
CON4 "CONNECTER_THREAD4_9P9X5_1110X92" THREAD4_9P9X5_1110X920 675,400 r0 top
CON5 "CONNECTER_THREAD4_9P9X5_1110X92" THREAD4_9P9X5_1110X920 580,4760 r90 top
CON6 "CONNECTER_THREAD4_9P9X5_1110X92" THREAD4_9P9X5_1110X920 580,5835 r270 top
D1 "DIODE_0_SOD-123_1N4148W" SOD-123#1 8495,830 r0 bottom
D2 "DIODE_0_SOD-123_1N4148W" SOD-123#1 8495,3445 r0 bottom
D3 "BAS21/SOT_1_SOD-123_MBR0530TR" SOD-123#2 2510,745 r180 top
D4 "DIODE ZENER_0_SOD-123_DNP" SOD-123#2 3125,775 r0 top
D5 "BAS21/SOT_1_SOD-123_BAT46W-E3-G" SOD-123#2 2270,625 r180 top
D6 "BAS21/SOT_1_SOD-123_MBR0530TR" SOD-123#2 3915,755 r180 top
D7 "DIODE ZENER_0_SOD-123_DNP" SOD-123#2 4525,775 r0 top
D8 "BAS21/SOT_1_SOD-123_MBR0530TR" SOD-123#2 5305,755 r180 top
D9 "BAS21/SOT_1_SOD-123_BAT46W-E3-G" SOD-123#2 3670,625 r180 top
D10 "DIODE ZENER_0_SOD-123_DNP" SOD-123#2 5925,775 r0 top
D11 "BAS21/SOT_1_SOD-123_BAT46W-E3-G" SOD-123#2 5070,625 r180 top
D12 "DIODE_0_SOD-123_1N4148W" SOD-123#1 8495,2145 r0 bottom
D13 "DIODE_0_SOD-123_SL14PL-TP" SOD-123#2 13255.68,1835 r0 top
D14 "DIODE_0_SOD-123_SL14PL-TP" SOD-123#2 13260,2830 r0 top
D15 "DIODE_0_SOD-123_SL14PL-TP" SOD-123#2 13260,6680 r0 top
D16 "DIODE_0_SOD-123_SL14PL-TP" SOD-123#2 13255,5655 r0 top
D17 "DIODE_0_SOD-123_SL14PL-TP" SOD-123#2 13260,3730 r0 top
D18 "DIODE_0_SOD-123_SL14PL-TP" SOD-123#2 13260,4755 r0 top
F1 "FUSE_0_FULSE_25A" FULSE 825,2650 r180 top
F2 "FUSE_0_FULSE_25A" FULSE 825,2350 r180 top
F3 "FUSE_0_FULSE_25A" FULSE 825,1950 r180 top
F4 "FUSE_0_FULSE_25A" FULSE 825,1650 r180 top
F5 "FUSE_0_FULSE_25A" FULSE 825,1250 r180 top
F6 "FUSE_0_FULSE_25A" FULSE 825,950 r180 top
F7 "FUSE_0_FULSE_25A" FULSE 9300,4870 r0 top
F8 "FUSE_0_FULSE_25A" FULSE 9299.35,5200 r0 top
ID-BOARD "#DEV" ID-BOARD 13925,7100 r0 top
ID-BOARD "#DEV" ID-BOARD 880,7100 r0 top
ID-BOARD "#DEV" ID-BOARD 14150,525 r0 top
ID-BOARD "#DEV" ID-BOARD 13925,7100 r0 bottom
ID-BOARD "#DEV" ID-BOARD 880,7100 r0 bottom
ID-BOARD "#DEV" ID-BOARD 14150,525 r0 bottom
J1 "CON24A_CON_2MM54_12X2_CON24A" CON_2MM54_12X2 9350,180 r0 top
J2 "CON12A_CON_2MM54_6X2_CON12A" CON_2MM54_6X2 6750,180 r180 top
J3 "CON2_CON_5MM_2X1_CON2" CON_5MM_2X1 13125,200 r0 top
J4 "CON10A_CON_2MM54_5X2_CON10A" CON_2MM54_5X2 11884.1,256.89 r180 top
J5 "CON5_CON_2MM54_5X1_CON5" CON_2MM54_5X1 10800,306.89 r180 top
L2 "126LNS_1_L71MM_8U" L71MM 10875,2100 r90 top
L3 "126LNS_1_L71MM_8U" L71MM 10875,6100 r90 top
L4 "126LNS_1_L71MM_8U" L71MM 10875,4100 r90 top
MT1 "CON1_2_MTH122_T1T2" MTH122 150,150 r90 top
MT2 "CON1_2_MTH122_T1T2" MTH122 14261,7180.3 r90 top
MT3 "CON1_2_MTH122_T1T2" MTH122 150,7180.3 r90 top
MTH122 "CON1_2_MTH122_T1T2" MTH122 14261,150 r90 top
MTH122 "CON1_2_MTH122_T1T2" MTH122 5200,4475 r90 top
MTH122 "CON1_2_MTH122_T1T2" MTH122 275,3150 r90 top
MTH122 "CON1_2_MTH122_T1T2" MTH122 9025,6675 r90 top
MTH122 "CON1_2_MTH122_T1T2" MTH122 5600,1275 r90 top
NTH236 "" NTH236 12401.82,1887.5 r0 bottom
NTH236 "" NTH236 12401.82,3812.5 r0 bottom
NTH236 "" NTH236 12401.82,5737.5 r0 bottom
Q1 "2N7002/SOT_SOT-23_2N7002K" SOT-23 8845,1130 r0 bottom
Q2 "2N7002/SOT_SOT-23_2N7002K" SOT-23 8575,380 r90 bottom
Q3 "2N7002/SOT_SOT-23_2N7002K" SOT-23 7750,405 r90 bottom
Q4 "2N7002/SOT_SOT-23_2N7002K" SOT-23 8845,3745 r0 bottom
Q5 "2N7002/SOT_SOT-23_2N7002K" SOT-23 8575,630 r90 bottom
Q6 "2N7002/SOT_SOT-23_2N7002K" SOT-23 7750,655 r90 bottom
Q7 "C3M0065090J_4_TO-247-4L_C3M0032" TO-247-4L 12710.68,1375 r90 bottom
Q8 "C3M0065090J_4_TO-247-4L_C3M0032" TO-247-4L 12710.68,5225 r90 bottom
Q9 "C3M0065090J_4_TO-247-4L_C3M0021" TO-247-4L 12710.68,3300 r90 bottom
Q10 "C3M0065090J_4_TO-247-4L_C3M0032" TO-247-4L 12710.68,6250 r90 bottom
Q11 "C3M0065090J_4_TO-247-4L_C3M0032" TO-247-4L 12710.68,2400 r90 bottom
Q12 "C3M0065090J_4_TO-247-4L_C3M0021" TO-247-4L 12710.68,4325 r90 bottom
Q15 "2N7002/SOT_SOT-23_2N7002K" SOT-23 8845,2445 r0 bottom
R1 "R_2_R1206_360K" R1206 1600,2800 r270 bottom
R2 "R_2_R1206_360K" R1206 4095,3660 r0 bottom
R3 "R_2_R1206_360K" R1206 7320,2700 r90 bottom
R4 "R_2_R1206_360K" R1206 1600,3000 r270 bottom
R5 "R_2_R1206_360K" R1206 3895,3660 r0 bottom
R6 "R_2_R1206_360K" R1206 7320,2500 r90 bottom
R7 "R_2_R1206_360K" R1206 1600,3200 r270 bottom
R8 "R_2_R1206_360K" R1206 3695,3660 r0 bottom
R9 "R_2_R1206_360K" R1206 7320,2300 r90 bottom
R10 "R_2_R1206_360K" R1206 1600,2050 r90 bottom
R11 "R_2_R1206_360K" R1206 4096,4143 r0 bottom
R12 "R_2_R1206_360K" R1206 7320,3800 r90 bottom
R13 "R_2_R1206_360K" R1206 1600,1850 r90 bottom
R14 "R_2_R1206_360K" R1206 3896,4143 r0 bottom
R15 "R_2_R1206_360K" R1206 7320,3600 r90 bottom
R16 "R_2_R1206_360K" R1206 1600,1650 r90 bottom
R17 "R_2_R1206_360K" R1206 3696,4143 r0 bottom
R18 "R_2_R1206_360K" R1206 7320,3400 r90 bottom
R19 "R_2_R1206_360K" R1206 1600,550 r270 bottom
R20 "R_2_R1206_360K" R1206 3700,1330 r180 bottom
R21 "R_2_R1206_360K" R1206 7320,1575 r90 bottom
R22 "R_2_R1206_360K" R1206 1600,750 r270 bottom
R23 "R_2_R1206_360K" R1206 3900,1330 r180 bottom
R24 "R_2_R1206_360K" R1206 7320,1375 r90 bottom
R25 "R_2_R1206_360K" R1206 1600,950 r270 bottom
R26 "R_2_R1206_360K" R1206 4100,1330 r180 bottom
R27 "R_2_R1206_360K" R1206 7320,1175 r90 bottom
R28 "RESISTOR_R1206_220K" R1206 5020,2455 r180 bottom
R29 "RESISTOR_R1206_220K" R1206 4825,2455 r180 bottom
R33 "RESISTOR_R1206_15R" R1206 8370,1130 r90 bottom
R34 "RESISTOR_R1206_15R" R1206 8460,1130 r270 bottom
R35 "RESISTOR_R1206_15R" R1206 8550,1130 r90 bottom
R36 "RESISTOR_R0603_0R" R0603 8550,230 r0 bottom
R37 "RESISTOR_R1206_220K" R1206 5020,2230 r180 bottom
R38 "RESISTOR_R1206_220K" R1206 4825,2230 r180 bottom
R42 "RESISTOR_R1206_22" R1206 8745,830 r0 bottom
R43 "RESISTOR_R0603_10K" R0603 8650,255 r270 bottom
R44 "RESISTOR_R0603_10K" R0603 8695,1105 r90 bottom
R45 "RESISTOR_R1206_220K" R1206 5020,1910 r180 bottom
R46 "RESISTOR_R1206_220K" R1206 4825,1910 r180 bottom
R50 "RESISTOR_R0603_1K" R0603 8670,1005 r0 bottom
R51 "RESISTOR_R0603_10K" R0603 8550,280 r0 bottom
R52 "RESISTOR_R0603_1K" R0603 7750,305 r180 bottom
R53 "RESISTOR_R0603_20K" R0603 8425,355 r270 bottom
R54 "RESISTOR_R1206_15R" R1206 8370,3745 r90 bottom
R55 "RESISTOR_R1206_15R" R1206 8470,3745 r270 bottom
R56 "RESISTOR_R1206_15R" R1206 8570,3745 r90 bottom
R57 "RESISTOR_R0603_0R" R0603 8550,480 r0 bottom
R58 "RESISTOR_R0603_220R" R0603 7600,280 r270 bottom
R59 "RESISTOR_R0603_10K" R0603 7600,405 r270 bottom
R60 "RESISTOR_R1206_22" R1206 8745,3445 r0 bottom
R61 "RESISTOR_R0603_5K" R0603 8650,505 r270 bottom
R62 "RESISTOR_R0603_10K" R0603 8695,3720 r90 bottom
R63 "RESISTOR_R0603_1K" R0603 8670,3620 r0 bottom
R64 "RESISTOR_R0603_10K" R0603 8550,530 r0 bottom
R65 "RESISTOR_R0603_1K" R0603 7750,555 r180 bottom
R66 "RESISTOR_R0603_20K" R0603 8425,605 r270 bottom
R67 "RESISTOR_R0603_220R" R0603 7600,530 r270 bottom
R68 "RESISTOR_R0603_10K" R0603 7600,655 r270 bottom
R69 "R_R1206_6R8" R1206 13235.68,1725 r180 top
R70 "R_R1206_6R8" R1206 13235.68,5545 r180 top
R71 "R_R1206_6R8" R1206 13235.68,3620 r180 top
R72 "RESISTOR_R1206_0R" R1206 5982.76,2035.75 r90 bottom
R73 "RESISTOR_R1206_0" R1206 6077.76,2035.75 r90 bottom
R74 "R_R0603_10K" R0603 13410.68,1525 r90 bottom
R75 "R_R0603_10K" R0603 13410.68,5375 r90 bottom
R76 "R_R0603_10K" R0603 13410.68,3450 r90 bottom
R77 "RESISTOR_R1206_620K" R1206 6077.76,1835.75 r90 bottom
R78 "RESISTOR_R1206_620K" R1206 5982.76,1835.75 r90 bottom
R79 "RESISTOR_R1206_620K" R1206 6077.76,1635.75 r90 bottom
R80 "RESISTOR_R1206_620K" R1206 5982.76,1635.75 r90 bottom
R81 "RESISTOR_R1206_620K" R1206 6077.76,1435.75 r90 bottom
R82 "R_R1206_6R8" R1206 13235.68,6570 r180 top
R83 "RESISTOR_R1206_620K" R1206 5982.76,1435.75 r90 bottom
R84 "RESISTOR_R1206_620K" R1206 6077.76,1235.75 r90 bottom
R85 "R_R1206_6R8" R1206 13235.68,4645 r180 top
R86 "R_R1206_6R8" R1206 13235.68,2720 r180 top
R87 "R_R0603_10K" R0603 13410.68,6400 r90 bottom
R88 "R_R0603_10K" R0603 13410.68,4475 r90 bottom
R89 "RESISTOR_R1206_620K" R1206 5982.76,1235.75 r90 bottom
R90 "RESISTOR_R1206_620K" R1206 6077.76,1035.75 r90 bottom
R91 "R_R0603_10K" R0603 13410.68,2550 r90 bottom
R92 "RESISTOR_R1206_620K" R1206 5982.76,1035.75 r90 bottom
R93 "RESISTOR_R1206_620K" R1206 6077.76,835.75 r90 bottom
R94 "RESISTOR_R1206_620K" R1206 5982.76,835.75 r90 bottom
R95 "R_R0603_10R" R0603 1000,3750 r180 top
R96 "R_R0603_6.8K" R0603 900,3825 r90 top
R97 "R_R0603_10K" R0603 880,3735 r180 top
R98 "R_R0603_10R" R0603 9145,790 r0 bottom
R99 "R_R0603_6.8K" R0603 9245,865 r90 bottom
R100 "R_R0603_10K" R0603 9270,765 r0 bottom
R101 "R_R0603_1.8K" R0603 850,3825 r270 top
R102 "R_R0603_1.8K" R0603 9295,865 r270 bottom
R103 "R_R0603_10R" R0603 9145,3405 r0 bottom
R104 "R_R0603_6.8K" R0603 9245,3480 r90 bottom
R105 "R_R0603_10K" R0603 9270,3380 r0 bottom
R106 "R_R0603_10R" R0603 9145,2105 r0 bottom
R107 "R_R0603_6.8K" R0603 9245,2180 r90 bottom
R108 "R_R0603_10K" R0603 9270,2080 r0 bottom
R109 "R_R0603_1.8K" R0603 9295,3480 r270 bottom
R110 "R_R0603_1.8K" R0603 9295,2180 r270 bottom
R111 "RESISTOR_R0805_1R" R0805 14300,2375 r90 bottom
R112 "RESISTOR_R0805_1R" R0805 14300,1350 r90 bottom
R113 "RESISTOR_R0805_1R" R0805 14300,6225 r90 bottom
R114 "RESISTOR_R0805_1R" R0805 14300,5200 r90 bottom
R115 "RESISTOR_R0805_1R" R0805 14300,4300 r90 bottom
R116 "RESISTOR_R0805_1R" R0805 14300,3275 r90 bottom
R117 "R_R0603_10R" R0603 13950,5300 r180 top
R118 "RESISTOR_R0603_100" R0603 14050,5475 r90 top
R119 "RESISTOR_R0603_4.7K" R0603 13950,5500 r0 top
R120 "R_R0805_1R" R0805 13655.34,5375 r270 bottom
R121 "R_R0603_10R" R0603 13950,6325 r180 top
R122 "RESISTOR_R0603_100" R0603 14050,6500 r90 top
R123 "RESISTOR_R0603_4.7K" R0603 13950,6525 r0 top
R124 "R_R0805_1R" R0805 13655.34,6400 r270 bottom
R125 "R_R0603_10R" R0603 13950,1450 r180 top
R126 "RESISTOR_R0603_100" R0603 14050,1625 r90 top
R127 "RESISTOR_R0603_4.7K" R0603 13950,1650 r0 top
R128 "R_R0805_1R" R0805 13655.34,1525 r270 bottom
R129 "R_R0603_10R" R0603 13950,2475 r180 top
R130 "RESISTOR_R0603_100" R0603 14050,2650 r90 top
R131 "RESISTOR_R0603_4.7K" R0603 13950,2675 r0 top
R132 "R_R0805_1R" R0805 13655.34,2550 r270 bottom
R133 "R_R0603_10R" R0603 13950,3375 r180 top
R134 "RESISTOR_R0603_100" R0603 14050,3550 r90 top
R135 "R_R0805_1R" R0805 13655.34,3450 r270 bottom
R136 "RESISTOR_R0603_4.7K" R0603 13950,3575 r0 top
R137 "R_R0603_10R" R0603 13950,4400 r180 top
R138 "RESISTOR_R0603_100" R0603 14050,4575 r90 top
R139 "RESISTOR_R0603_4.7K" R0603 13950,4600 r0 top
R140 "R_R0805_1R" R0805 13655.34,4475 r270 bottom
R141 "RESISTOR_R0603_4.7" R0603 3225,300 r90 bottom
R142 "RESISTOR_R0603_4.7" R0603 2935,725 r270 top
R143 "RESISTOR_R0603_4.7" R0603 3225,175 r270 bottom
R144 "RESISTOR_R0603_10K" R0603 3125,175 r270 bottom
R145 "RESISTOR_R0603_10K" R0603 3175,175 r90 bottom
R146 "RESISTOR_R1206_220K" R1206 2025,525 r180 top
R147 "RESISTOR_R0603_47K" R0603 2300,525 r270 top
R148 "RESISTOR_R0603_470R" R0603 2200,525 r270 top
R149 "RESISTOR_R0603_100R" R0603 2150,525 r270 top
R150 "RESISTOR_R0603_100R" R0603 2250,525 r270 top
R151 "RESISTOR_R0603_10K" R0603 3025,175 r90 bottom
R152 "RESISTOR_R1206_1.5K" R1206 2025,625 r180 top
R153 "RESISTOR_R0603_DNP" R0603 2050,700 r180 top
R154 "RESISTOR_R0603_10K" R0603 3100,440 r0 bottom
R155 "RESISTOR_R0603_100R" R0603 2200,700 r180 top
R156 "RESISTOR_R0603_DNP" R0603 2200,750 r180 top
R157 "RESISTOR_R0603_4.7" R0603 4625,300 r90 bottom
R158 "RESISTOR_R0603_4.7" R0603 4310,725 r90 top
R159 "RESISTOR_R0603_4.7" R0603 4625,175 r270 bottom
R160 "RESISTOR_R0603_10K" R0603 4475,175 r270 bottom
R161 "RESISTOR_R0603_10K" R0603 4575,175 r90 bottom
R162 "RESISTOR_R0603_10K" R0603 4425,175 r90 bottom
R163 "RESISTOR_R1206_220K" R1206 3425,525 r180 top
R164 "RESISTOR_R0603_10K" R0603 4500,440 r0 bottom
R165 "RESISTOR_R0603_47K" R0603 3700,525 r270 top
R166 "RESISTOR_R0603_470R" R0603 3600,525 r270 top
R167 "RESISTOR_R0603_100R" R0603 3550,525 r270 top
R168 "RESISTOR_R0603_100R" R0603 3650,525 r270 top
R169 "RESISTOR_R1206_1.5K" R1206 3425,625 r180 top
R170 "RESISTOR_R0603_DNP" R0603 3450,700 r180 top
R171 "RESISTOR_R0603_4.7" R0603 5700,725 r270 top
R172 "RESISTOR_R0603_4.7" R0603 6025,300 r90 bottom
R173 "RESISTOR_R0603_10K" R0603 5925,175 r270 bottom
R174 "RESISTOR_R0603_4.7" R0603 6025,175 r270 bottom
R175 "RESISTOR_R0603_100R" R0603 3615,700 r180 top
R176 "RESISTOR_R0603_DNP" R0603 3615,750 r180 top
R177 "RESISTOR_R0603_10K" R0603 5975,175 r90 bottom
R178 "RESISTOR_R0603_10K" R0603 5825,175 r90 bottom
R179 "RESISTOR_R0603_10K" R0603 5900,440 r0 bottom
R181 "RESISTOR_R1206_220K" R1206 4825,525 r180 top
R183 "RESISTOR_R0603_47K" R0603 5100,525 r270 top
R184 "RESISTOR_R0603_470R" R0603 5000,525 r270 top
R185 "RESISTOR_R0603_100R" R0603 4950,525 r270 top
R186 "RESISTOR_R0603_100R" R0603 5050,525 r270 top
R187 "RESISTOR_R1206_1.5K" R1206 4825,625 r180 top
R188 "RESISTOR_R0603_DNP" R0603 4850,700 r180 top
R189 "RESISTOR_R0603_100R" R0603 5000,700 r180 top
R190 "RESISTOR_R0603_DNP" R0603 5000,750 r180 top
R191 "RESISTOR_R0603_0R" R0603 8540,2580 r0 bottom
R198 "RESISTOR_R0603_10K" R0603 8695,2420 r90 bottom
R199 "RESISTOR_R1206_15R" R1206 8370,2445 r90 bottom
R200 "RESISTOR_R1206_15R" R1206 8570,2445 r90 bottom
R201 "RESISTOR_R0603_1K" R0603 8670,2320 r0 bottom
R202 "RESISTOR_R1206_15R" R1206 8470,2445 r270 bottom
R203 "RESISTOR_R1206_22" R1206 8745,2145 r0 bottom
R204 "RESISTOR_R1206_200K" R1206 7465,5330 r270 bottom
R205 "RESISTOR_R1206_200K" R1206 8835,5330 r270 bottom
R206 "RESISTOR_R1206_200K" R1206 7465,5130 r270 bottom
R207 "RESISTOR_R1206_200K" R1206 8835,5130 r270 bottom
R208 "RESISTOR_R1206_200K" R1206 7465,5530 r270 bottom
R209 "RESISTOR_R1206_200K" R1206 8835,5530 r270 bottom
R210 "RESISTOR_R1206_200K" R1206 8150,6380 r270 bottom
R211 "RESISTOR_R1206_200K" R1206 2310,6380 r270 bottom
R212 "RESISTOR_R1206_200K" R1206 8150,6580 r270 bottom
R213 "RESISTOR_R1206_200K" R1206 2310,6580 r270 bottom
R214 "RESISTOR_R1206_200K" R1206 8150,6780 r270 bottom
R215 "RESISTOR_R1206_200K" R1206 2310,6780 r270 bottom
R216 "RESISTOR_R1206_200K" R1206 3035,5305 r270 bottom
R217 "RESISTOR_R1206_200K" R1206 4460,5305 r270 bottom
R218 "RESISTOR_R1206_200K" R1206 3035,5105 r270 bottom
R219 "RESISTOR_R1206_200K" R1206 3035,5505 r270 bottom
R220 "RESISTOR_R1206_200K" R1206 4460,5105 r270 bottom
R221 "RESISTOR_R1206_200K" R1206 4460,5505 r270 bottom
R222 "RESISTOR_R1206_200K" R1206 3735,6380 r270 bottom
R223 "RESISTOR_R1206_200K" R1206 6585,6380 r270 bottom
R224 "RESISTOR_R1206_200K" R1206 6585,6580 r270 bottom
R225 "RESISTOR_R1206_200K" R1206 3735,6580 r270 bottom
R226 "RESISTOR_R1206_200K" R1206 3735,6780 r270 bottom
R227 "RESISTOR_R1206_200K" R1206 6585,6780 r270 bottom
R228 "RESISTOR_R1206_200K" R1206 7310,5330 r270 bottom
R229 "RESISTOR_R1206_200K" R1206 7310,5130 r270 bottom
R230 "RESISTOR_R1206_200K" R1206 7310,5530 r270 bottom
R231 "RESISTOR_R1206_200K" R1206 5885,5305 r270 bottom
R232 "RESISTOR_R1206_200K" R1206 5885,5105 r270 bottom
R233 "RESISTOR_R1206_200K" R1206 5885,5505 r270 bottom
R234 "RESISTOR_R1206_200K" R1206 8010,6380 r270 bottom
R235 "RESISTOR_R1206_200K" R1206 8010,6580 r270 bottom
R236 "RESISTOR_R1206_200K" R1206 8010,6780 r270 bottom
R237 "RESISTOR_R1206_200K" R1206 5160,6380 r270 bottom
R238 "RESISTOR_R1206_200K" R1206 5160,6580 r270 bottom
R239 "RESISTOR_R1206_200K" R1206 5160,6780 r270 bottom
R240 "RESISTOR_R1206_220K" R1206 2250,625 r180 bottom
R241 "RESISTOR_R1206_220K" R1206 3650,625 r180 bottom
R242 "RESISTOR_R1206_220K" R1206 5070,625 r180 bottom
R243 "RESISTOR_R1206_220K" R1206 4825,2135 r180 bottom
R244 "RESISTOR_R1206_220K" R1206 4825,1815 r180 bottom
R245 "RESISTOR_R1206_220K" R1206 4825,2550 r180 bottom
R258 "R_R1206_10R" R1206 13090,1780 r90 top
R259 "R_R1206_10R" R1206 13090,2775 r90 top
R260 "R_R1206_10R" R1206 13090,6625 r90 top
R261 "R_R1206_10R" R1206 13090,5600 r90 top
R262 "R_R1206_10R" R1206 13090,3675 r90 top
R263 "R_R1206_10R" R1206 13090,4700 r90 top
R264 "RESISTOR_R1206_220K" R1206 5020,2135 r180 bottom
R265 "RESISTOR_R1206_220K" R1206 5020,1815 r180 bottom
R266 "RESISTOR_R1206_220K" R1206 5020,2550 r180 bottom
R267 "RESISTOR_R1206_NA" R1206 150,395 r270 top
RLY1 "RELAY SPST_1_T9SV1K15-12_832HA-" T9SV1K15-12 8637.99,1331.73 r0 top
RLY2 "RELAY SPST_1_T9SV1K15-12_832HA-" T9SV1K15-12 8637.99,3946.73 r0 top
RLY3 "RELAY SPST_1_T9SV1K15-12_832HA-" T9SV1K15-12 8637.99,2646.73 r0 top
RV1 "VARISTOR_NTC_OD20MM_NTC" NTC_OD20MM 6425,1550 r90 top
RV2 "VARISTOR_NTC_OD20MM_NTC" NTC_OD20MM 6725,1550 r270 top
RV3 "VARISTOR_NTC_OD20MM_NTC" NTC_OD20MM 6756,4381 r180 top
RV4 "VARISTOR_NTC_OD20MM_NTC" NTC_OD20MM 7580,4381 r180 top
RV5 "VARISTOR_NTC_OD20MM_NTC" NTC_OD20MM 6725,750 r270 top
RV6 "VARISTOR_NTC_OD20MM_NTC" NTC_OD20MM 6425,750 r90 top
TP1 "CON1_2_TH47_CR98_T1T2" TH47_CR98 2260,4430 r0 top
TP2 "CON1_2_TH47_CR98_T1T2" TH47_CR98 1680,5675 r0 top
U1 "LEU169_TCLT1003_SOP-4L_TCLT1003" TCLT1003 8100,355 r0 bottom
U2 "LEU169_TCLT1003_SOP-4L_TCLT1003" TCLT1003 8100,605 r0 bottom
U3 "MCR1101_0_SOICW-16_ACS733" SOICW-16 850,4175 r270 top
U4 "MCR1101_0_SOICW-16_ACS733" SOICW-16 9295,1215 r270 bottom
U5 "MCR1101_0_SOICW-16_ACS733" SOICW-16 9295,3830 r270 bottom
U6 "MCR1101_0_SOICW-16_ACS733" SOICW-16 9295,2530 r270 bottom
U7 "MC78L05F-TP_SOT-89-3L_MC78L05F-" SOT-89-3L 10400,550 r90 top
U8 "MC78L05F-TP_TO252AB_LF50ABDT-TR" TO252AB 10259.61,915.19 r0 bottom
U9 "E1212S-2WR2_3_G1212S_2W11_R15P2" G1212S_2W11 13983.7,2171.6 r180 top
U10 "E1212S-2WR2_3_G1212S_2W11_R15P2" G1212S_2W11 13983.7,1146.6 r180 top
U11 "E1212S-2WR2_3_G1212S_2W11_R15P2" G1212S_2W11 13983.7,6021.6 r180 top
U12 "E1212S-2WR2_3_G1212S_2W11_R15P2" G1212S_2W11 13983.7,4996.6 r180 top
U13 "E1212S-2WR2_3_G1212S_2W11_R15P2" G1212S_2W11 13983.7,4096.6 r180 top
U14 "E1212S-2WR2_3_G1212S_2W11_R15P2" G1212S_2W11 13983.7,3071.6 r180 top
U15 "UCC5350MC_SOIC8_DWV_UCC5350MC" SOIC8_DWV 13605.34,5425 r180 top
U16 "UCC5350MC_SOIC8_DWV_UCC5350MC" SOIC8_DWV 13605.34,6450 r180 top
U17 "UCC5350MC_SOIC8_DWV_UCC5350MC" SOIC8_DWV 13605.34,1575 r180 top
U18 "UCC5350MC_SOIC8_DWV_UCC5350MC" SOIC8_DWV 13605.34,2600 r180 top
U19 "UCC5350MC_SOIC8_DWV_UCC5350MC" SOIC8_DWV 13605.34,3500 r180 top
U20 "UCC5350MC_SOIC8_DWV_UCC5350MC" SOIC8_DWV 13605.34,4525 r180 top
U21 "LT3092EST_SOT223_5_SOT223_3_LT3" SOT223_3 2225,250 r180 top
U22 "PS_B0505XT_SMD-5_PS_B0505XT" SMD-5 2700,350 r90 top
U23 "24C16BT-I/SN_3_SSO-8_ACPL-C870-" SSO-8 3125,375 r180 top
U24 "MCP6031_SOT23-5_MCP6031" SOT23-5 3080,300 r270 bottom
U25 "PS_B0505XT_SMD-5_PS_B0505XT" SMD-5 4100,350 r90 top
U26 "24C16BT-I/SN_3_SSO-8_ACPL-C870-" SSO-8 4525,375 r180 top
U27 "MCP6031_SOT23-5_MCP6031" SOT23-5 4480,300 r270 bottom
U28 "LT3092EST_SOT223_5_SOT223_3_LT3" SOT223_3 3625,250 r180 top
U29 "PS_B0505XT_SMD-5_PS_B0505XT" SMD-5 5500,350 r90 top
U30 "24C16BT-I/SN_3_SSO-8_ACPL-C870-" SSO-8 5925,375 r180 top
U31 "MCP6031_SOT23-5_MCP6031" SOT23-5 5880,300 r270 bottom
U32 "LT3092EST_SOT223_5_SOT223_3_LT3" SOT223_3 5025,250 r180 top
VAR1 "VARISTOR_MOV_OD21P5MM_PI10MM_PI" MOV_OD21P5MM_PI10MM_PINV3P3MM 1150,2825 r270 top
VAR2 "VARISTOR_MOV_OD21P5MM_PI10MM_PI" MOV_OD21P5MM_PI10MM_PINV3P3MM 1185,1975 r90 top
VAR3 "VARISTOR_MOV_OD21P5MM_PI10MM_PI" MOV_OD21P5MM_PI10MM_PINV3P3MM 1150,975 r270 top
XC1 "CAP NP_CAPFILM_26_5X12MM_2.2UF" CAPFILM_26_5X12MM 1600,3000 r90 top
XC2 "CAP NP_CAPFILM_26_5X12MM_2.2UF" CAPFILM_26_5X12MM 3890,3660 r180 top
XC3 "CAP NP_CAPFILM_26_5X15MM_3.3UF" CAPFILM_26_5X15MM 7190,2500 r270 top
XC4 "CAP NP_CAPFILM_26_5X12MM_2.2UF" CAPFILM_26_5X12MM 1600,1850 r270 top
XC5 "CAP NP_CAPFILM_26_5X12MM_2.2UF" CAPFILM_26_5X12MM 3890,4145 r180 top
XC6 "CAP NP_CAPFILM_26_5X15MM_3.3UF" CAPFILM_26_5X15MM 7190,3600 r270 top
XC7 "CAP NP_CAPFILM_26_5X12MM_2.2UF" CAPFILM_26_5X12MM 1600,750 r90 top
XC8 "CAP NP_CAPFILM_26_5X12MM_2.2UF" CAPFILM_26_5X12MM 4785,1330 r180 top
XC9 "CAP NP_CAPFILM_26_5X15MM_3.3UF" CAPFILM_26_5X15MM 7190,1375 r270 top
XC10 "CAP NP_CAPFILM_26_5X15MM_3.3UF" CAPFILM_26_5X15MM 7800,1375 r270 top
XC11 "CAP NP_CAPFILM_26_5X15MM_3.3UF" CAPFILM_26_5X15MM 7795,3600 r270 top
XC12 "CAP NP_CAPFILM_26_5X15MM_3.3UF" CAPFILM_26_5X15MM 7800,2500 r270 top
YC1 "CAP NP_C1812_220P" C1812 200,2475 r0 bottom
YC2 "CAP NP_C1812_220P" C1812 1943,2978 r270 bottom
YC3 "CAP_C1812_220P" C1812 2752,2003 r90 bottom
YC4 "CAP NP_C1812_220P" C1812 200,1775 r0 bottom
YC5 "CAP NP_C1812_220P" C1812 1801,2255 r180 bottom
YC6 "CAP_C1812_220P" C1812 3416,2699 r0 bottom
YC7 "CAP NP_C1812_220P" C1812 200,1075 r0 bottom
YC8 "CAP_C1812_220P" C1812 2879,1598 r0 bottom
YC9 "CAP NP_C1812_220P" C1812 1200,475 r0 bottom
YC10 "CAP NP_C1812_220P" C1812 14170,6910 r180 top
YC11 "CAP NP_C1812_220P" C1812 490,6410 r270 top

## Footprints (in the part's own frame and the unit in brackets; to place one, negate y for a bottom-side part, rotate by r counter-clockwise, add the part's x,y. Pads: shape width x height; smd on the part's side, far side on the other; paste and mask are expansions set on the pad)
C0603 [mil] "C0603"
  rect 35x31 smd: 1(-29.92,0) 2(29.92,0)
  silkscreen extent -57,-26 57,26, body extent -32,-16 32,16, height 150
C0805 [mil] "C0805"
  rect 43x50 smd: 1(-35.04,0) 2(35.04,0)
  silkscreen extent -67,-35 67,35, body extent -39,-25 39,25, height 150
C1206 [mil] "C1206"
  rect 55x63 smd: 1(55.12,0) 2(-55.12,0)
  silkscreen extent -95,-45 95,45, body extent -63,-32 63,32, height 25
C1812 [mil] "C1812"
  rect 59x126 smd: 1(90.55,0) 2(-90.55,0)
  silkscreen extent -134,-75 173,75, body extent -89,-63 89,63, height 150
C2220 [mm] "C2220"
  rect 1.905x5.08 smd: 1(-3,0) 2(3,0)
  silkscreen extent -4.3,-2.85 4.3,2.85, body extent -2.8,-2.5 2.8,2.5, height 1.27
CAPFILM_26_5X12MM [mil] "CAPFILM_26_5X12MM"
  round 98 hole 39: 1(-442.91,0) 2(442.91,0)
  silkscreen extent -522,-236 522,236, body extent -522,-236 522,236, height 150
CAPFILM_26_5X15MM [mil] "CAPFILM_26_5X15MM"
  round 98 hole 39: 1(-442.91,0) 2(442.91,0)
  silkscreen extent -522,-295 522,295, body extent -522,-295 522,295, height 150
CAPFILM_31_5X12_5MM [mil] "CAPFILM_31_5X12_5MM"
  round 138 hole 39: 1(-541.34,0) 2(541.34,0)
  silkscreen extent -630,-256 630,256
CM_4P [mm] "CM_4P"
  oval 5.5x3 hole 4.5 slot 2.6 at 90 deg: 1(-11,-8.5) 2(11,-8.5) 3(11,8.5) 4(-11,8.5)
  silkscreen extent -17.5,-13.2 17.5,11.7, body extent -17.5,-11.7 17.5,11.7, height 3.81
CON_2MM54_5X1 [mil] "CON_2MM54_5X1"
  round 59 hole 40: 1(-193.11,6.89) 2(-93.11,6.89) 3(6.89,6.89) 4(106.89,6.89) 5(206.89,6.89)
  silkscreen extent -262,-62 262,62, body extent -267,-67 267,67, height 150
CON_2MM54_5X2 [mil] "CON_2MM54_5X2"
  round 59 hole 40: 1(-193.11,-43.11) 2(-193.11,56.89) 3(-93.11,-43.11) 4(-93.11,56.89) 5(6.89,-43.11) 6(6.89,56.89) 7(106.89,-43.11) 8(106.89,56.89) 9(206.89,-43.11) 10(206.89,56.89)
  silkscreen extent -262,-112 262,112, body extent -267,-117 267,117, height 150
CON_2MM54_6X2 [mil] "CON_2MM54_6X2"
  round 59 hole 39: 1(-250,-50) 2(-250,50) 3(-150,-50) 4(-150,50) 5(-50,-50) 6(-50,50) 7(50,-50) 8(50,50) 9(150,-50) 10(150,50) 11(250,-50) 12(250,50)
  silkscreen extent -310,-110 310,110, body extent -310,-110 310,110, height 150
CON_2MM54_12X2 [mil] "CON_2MM54_12X2"
  round 59 hole 39: 1(-550,-50) 2(-550,50) 3(-450,-50) 4(-450,50) 5(-350,-50) 6(-350,50) 7(-250,-50) 8(-250,50) 9(-150,-50) 10(-150,50) 11(-50,-50) 12(-50,50) 13(50,-50) 14(50,50) 15(150,-50) 16(150,50) 17(250,-50) 18(250,50) 19(350,-50) 20(350,50) 21(450,-50) 22(450,50) 23(550,-50) 24(550,50)
  silkscreen extent -610,-110 610,110
CON_5MM_2X1 [mil] "CON_5MM_2X1"
  round 98 hole 47: 1(-99.22,17.71) 2(97.64,17.71)
  silkscreen extent -198,-178 198,148
ECAP_D8P3_5 [mil] "ECAP_D8P3_5"
  rect 50x50 hole 32: 1(-68.9,0)
  round 50 hole 32: 2(68.9,0)
  silkscreen extent -157,-169 169,169, body extent -158,-158 158,158, height 150
ECAP_D35P7_25 [mil] "ECAP_D35P7_25"
  rect 120x120 / inner round 91 / far side rect 120x120 hole 79: 1(-196.85,0)
  round 120 / inner round 91 / far side round 120 hole 79: 2(196.85,0)
  silkscreen extent -700,-689 689,689, body extent -689,-689 689,689, height 2500
FULSE [mil] "FULSE"
  round 80 hole 59: 1(75.78,66.43) 2(-75.78,-66.43)
  silkscreen extent -42,-52 194,185, body extent -124,-114 194,185, height 1000
G1212S_2W11 [mil] "G1212S_2W11"
  round 59 hole 40: 1(-300.55,113.53) 2(-200.55,113.53) 5(99.45,113.53) 6(199.45,113.53) 7(299.45,113.53)
  silkscreen extent -386,-194 383,192, body extent -385,-193 385,193, height 150
ID-BOARD [mil] "ID-BOARD"
  TOP region: 0,20 -7.65,18.48 -14.14,14.14 -18.48,7.65 -20,0 -20,0 -18.48,-7.65 -14.14,-14.14 -7.65,-18.48 0,-20 0,-20 7.65,-18.48 14.14,-14.14 18.48,-7.65 20,0 20,0 18.48,7.65 14.14,14.14 7.65,18.48 0,20
  TOP keep-out circle w40: c0,0 r40
  BOTTOM region: 0,20 7.65,18.48 14.14,14.14 18.48,7.65 20,0 20,0 18.48,-7.65 14.14,-14.14 7.65,-18.48 0,-20 0,-20 -7.65,-18.48 -14.14,-14.14 -18.48,-7.65 -20,0 -20,0 -18.48,7.65 -14.14,14.14 -7.65,18.48 0,20
  silkscreen extent -61,-61 61,61, body extent -61,-61 61,61, height 150
L71MM [mil] "L71MM"
  oval 180x300 / inner oval 122x232 / far side oval 180x300 hole 110 slot 220 at 90 deg: 1(-767.72,-1060) 3(767.72,0)
  silkscreen extent -925,-1378 925,1378, body extent -900,-1350 900,1350, height 150
LCM1 [mil] "LCM1"
  oval 300x180 / inner oval 232x122 / far side oval 300x180 hole 110 slot 220 at 0 deg: 1(0,-1082.68) 2(0,-314.96)
  oval 180x300 / inner oval 122x232 / far side oval 180x300 hole 220 slot 110 at 30 deg rot 30: 3(937.63,541.34) 4(272.76,157.48)
  oval 300x180 / inner oval 232x122 / far side oval 300x180 hole 110 slot 220 at 60 deg rot 60: 5(-937.63,541.34) 6(-272.76,157.48)
  silkscreen extent -1260,-1260 1260,1260, body extent -1260,-1260 1260,1260, height 50
MOV_OD21P5MM_PI10MM_PINV3P3MM [mil] "MOV_OD21P5MM_PI10MM_PINV3P3MM"
  round 100 hole 51: 1(-196.85,78.74) 2(196.85,-78.74)
  silkscreen extent -394,-154 394,154, body extent -395,-155 395,155, height 20
MTH122 [mil] "MTH122"
  round 180 hole 122: 1(0,0)
  silkscreen extent -109,-109 109,109, body extent -109,-109 109,109, height 150
NTC_OD20MM [mil] "NTC_OD20MM"
  round 100 hole 51: 1(-196.85,78.74) 2(196.85,-78.74)
  silkscreen extent -394,-154 394,154, body extent -394,-154 394,154, height 20
NTH236 [mil] "NTH236"
  round 236 hole 236 unplated: 1(0,0)
R0603 [mil] "R0603"
  rect 30x30 smd: 1(-29.92,0) 2(29.92,0)
  silkscreen extent -55,-26 55,26, body extent -32,-16 32,16, height 50
R0805 [mil] "R0805"
  rect 39x47 smd: 1(-39.37,0) 2(39.37,0)
  silkscreen extent -68,-32 68,32, body extent -39,-25 39,25, height 50
R1206 [mil] "R1206"
  rect 55x63 smd: 1(-55.12,0) 2(55.12,0)
  silkscreen extent -93,-41 93,41, body extent -61,-32 61,32, height 50
SMD-5 [mil] "SMD-5"
  rect 39x83 smd: 1(-150,-198.5) 2(-50,-198.5) 3(150,-198.5) 4(150,198.5) 5(-150,198.5)
  silkscreen extent -250,-280 250,164, body extent -251,-165 251,165, height 150
SOD-123#1 [mm] "SOD-123"
  rect 1.02x1.4 smd: 1(2.15,0) 2(-2.15,0)
  silkscreen extent -3.25,-1 3.89,1.88, body extent -3.05,-0.88 3.05,0.88, height 3.81
SOD-123#2 [mm] "SOD-123"
  rect 1.02x1.4 smd: 1(-2.15,0) 2(2.15,0)
  silkscreen extent -2.95,-1 3.25,1.85, body extent -3.05,-0.88 3.05,0.88, height 3.81
SOIC8_DWV [mil] "SOIC8_DWV"
  rect 70x25 smd: 1(-208.66,75) 2(-208.66,25) 3(-208.66,-25) 4(-208.66,-75) 5(208.66,-75) 6(208.66,-25) 7(208.66,25) 8(208.66,75)
  silkscreen extent -224,-117 150,123, body extent -247,-118 247,118, height 150
SOICW-16 [mil] "SOICW-16"
  oval 90x25 smd: 1(-180.24,175) 2(-180.24,125) 3(-180.24,75) 4(-180.24,25) 5(-180.24,-25) 6(-180.24,-75) 7(-180.24,-125) 8(-180.24,-175) 9(180.24,-175) 10(180.24,-125) 11(180.24,-75) 12(180.24,-25) 13(180.24,25) 14(180.24,75) 15(180.24,125) 16(180.24,175)
  silkscreen extent -265,-203 281,203, body extent -203,-203 203,203, height 150
SOT23-5 [mil] "SOT23-5"
  oval 24x52 smd: 1(-37.4,-49.21) 2(0,-49.21) 3(37.4,-49.21) 4(37.4,49.21) 5(-37.4,49.21)
  silkscreen extent -59,-109 59,83, body extent -57,-55 57,55, height 150
SOT223_3 [mil] "SOT223_3"
  rect 59x79 smd: 1(-90.55,-124.02) 2(0,-124.02) 3(90.55,-124.02)
  rect 150x79 smd: 4(0,124.02)
  silkscreen extent -132,-204 132,73, body extent -132,-167 132,167, height 150
SOT-23 [mil] "SOT-23"
  oval 24x50 smd: 1(-37.4,-39.76) 2(37.4,-39.76) 3(0,39.76)
  silkscreen extent -59,-105 59,75, body extent -60,-52 60,52, height 150
SOT-89-3L [mil] "SOT-89-3L"
  rect 63x24 smd: 1(-74.78,53.08) 3(-74.78,-65.03)
  rect 25x25 smd mask+0: 2(0,0)
  TOP region: -106,-20 -106,8 -27,8 -27,34 106,34 106,-45 -27,-45 -27,-20
  silkscreen extent -87,-97 51,97, body extent -109,-98 109,98, height 150
SSO-8 [mil] "SSO-8"
  rect 18x75 smd: 1(-74.84,-211.52) 2(-24.84,-211.52) 3(25.16,-211.52) 4(75.16,-211.52) 5(75.16,211.52) 6(25.16,211.52) 7(-24.84,211.52) 8(-74.84,211.52)
  silkscreen extent -118,-199 118,161, body extent -119,-252 119,252, height 150
T9SV1K15-12 [mil] "T9SV1K15-12"
  round 100 hole 59: 1(-232.28,-371.06) 2(169.3,-371.06)
  round 197 hole 87: 3(-381.88,128.94) 4(318.9,229.34)
  silkscreen extent -531,-631 531,629, body extent -535,-634 535,634, height 150
TCLT1003 [mil] "TCLT1003"
  oval 86x35 smd: 1(-197.83,50) 2(-197.83,-50) 3(197.83,-50) 4(197.83,50)
  silkscreen extent -281,-81 148,81, body extent -244,-82 244,82, height 150
TH47_CR98 [mil] "TH47_CR98"
  round 98 hole 47: 1(0,0)
  silkscreen extent -66,-66 66,66
THREAD4_9P9X5_1110X920 [mil] "THREAD4_9P9X5_1110X920"
  round 130 / inner round 99 / far side round 130 hole 87: 1(194.88,98.42) 2(-194.88,98.42) 3(-194.88,-98.42) 4(194.88,-98.42)
  silkscreen extent -219,-181 219,181, body extent -263,-182 263,182, height 150
TO252AB [mil] "TO252AB"
  rect 63x118 smd: 1(-90.55,167.4) 3(90.55,167.4)
  rect 264x264 smd: 2(0,-94.41)
  silkscreen extent -146,-239 150,264, body extent -135,-229 135,229, height 150
TO-247-4L [mm] "TO-247-4L"
  oval 3.302x5.004 hole 1.397: 1(-5.08,12.25)
  rrect40% 2x5 hole 1.346: 2(0,12.25) 3(2.54,12.25) 4(5.08,12.25)
  silkscreen extent -8.07,-15.75 8.07,15.75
